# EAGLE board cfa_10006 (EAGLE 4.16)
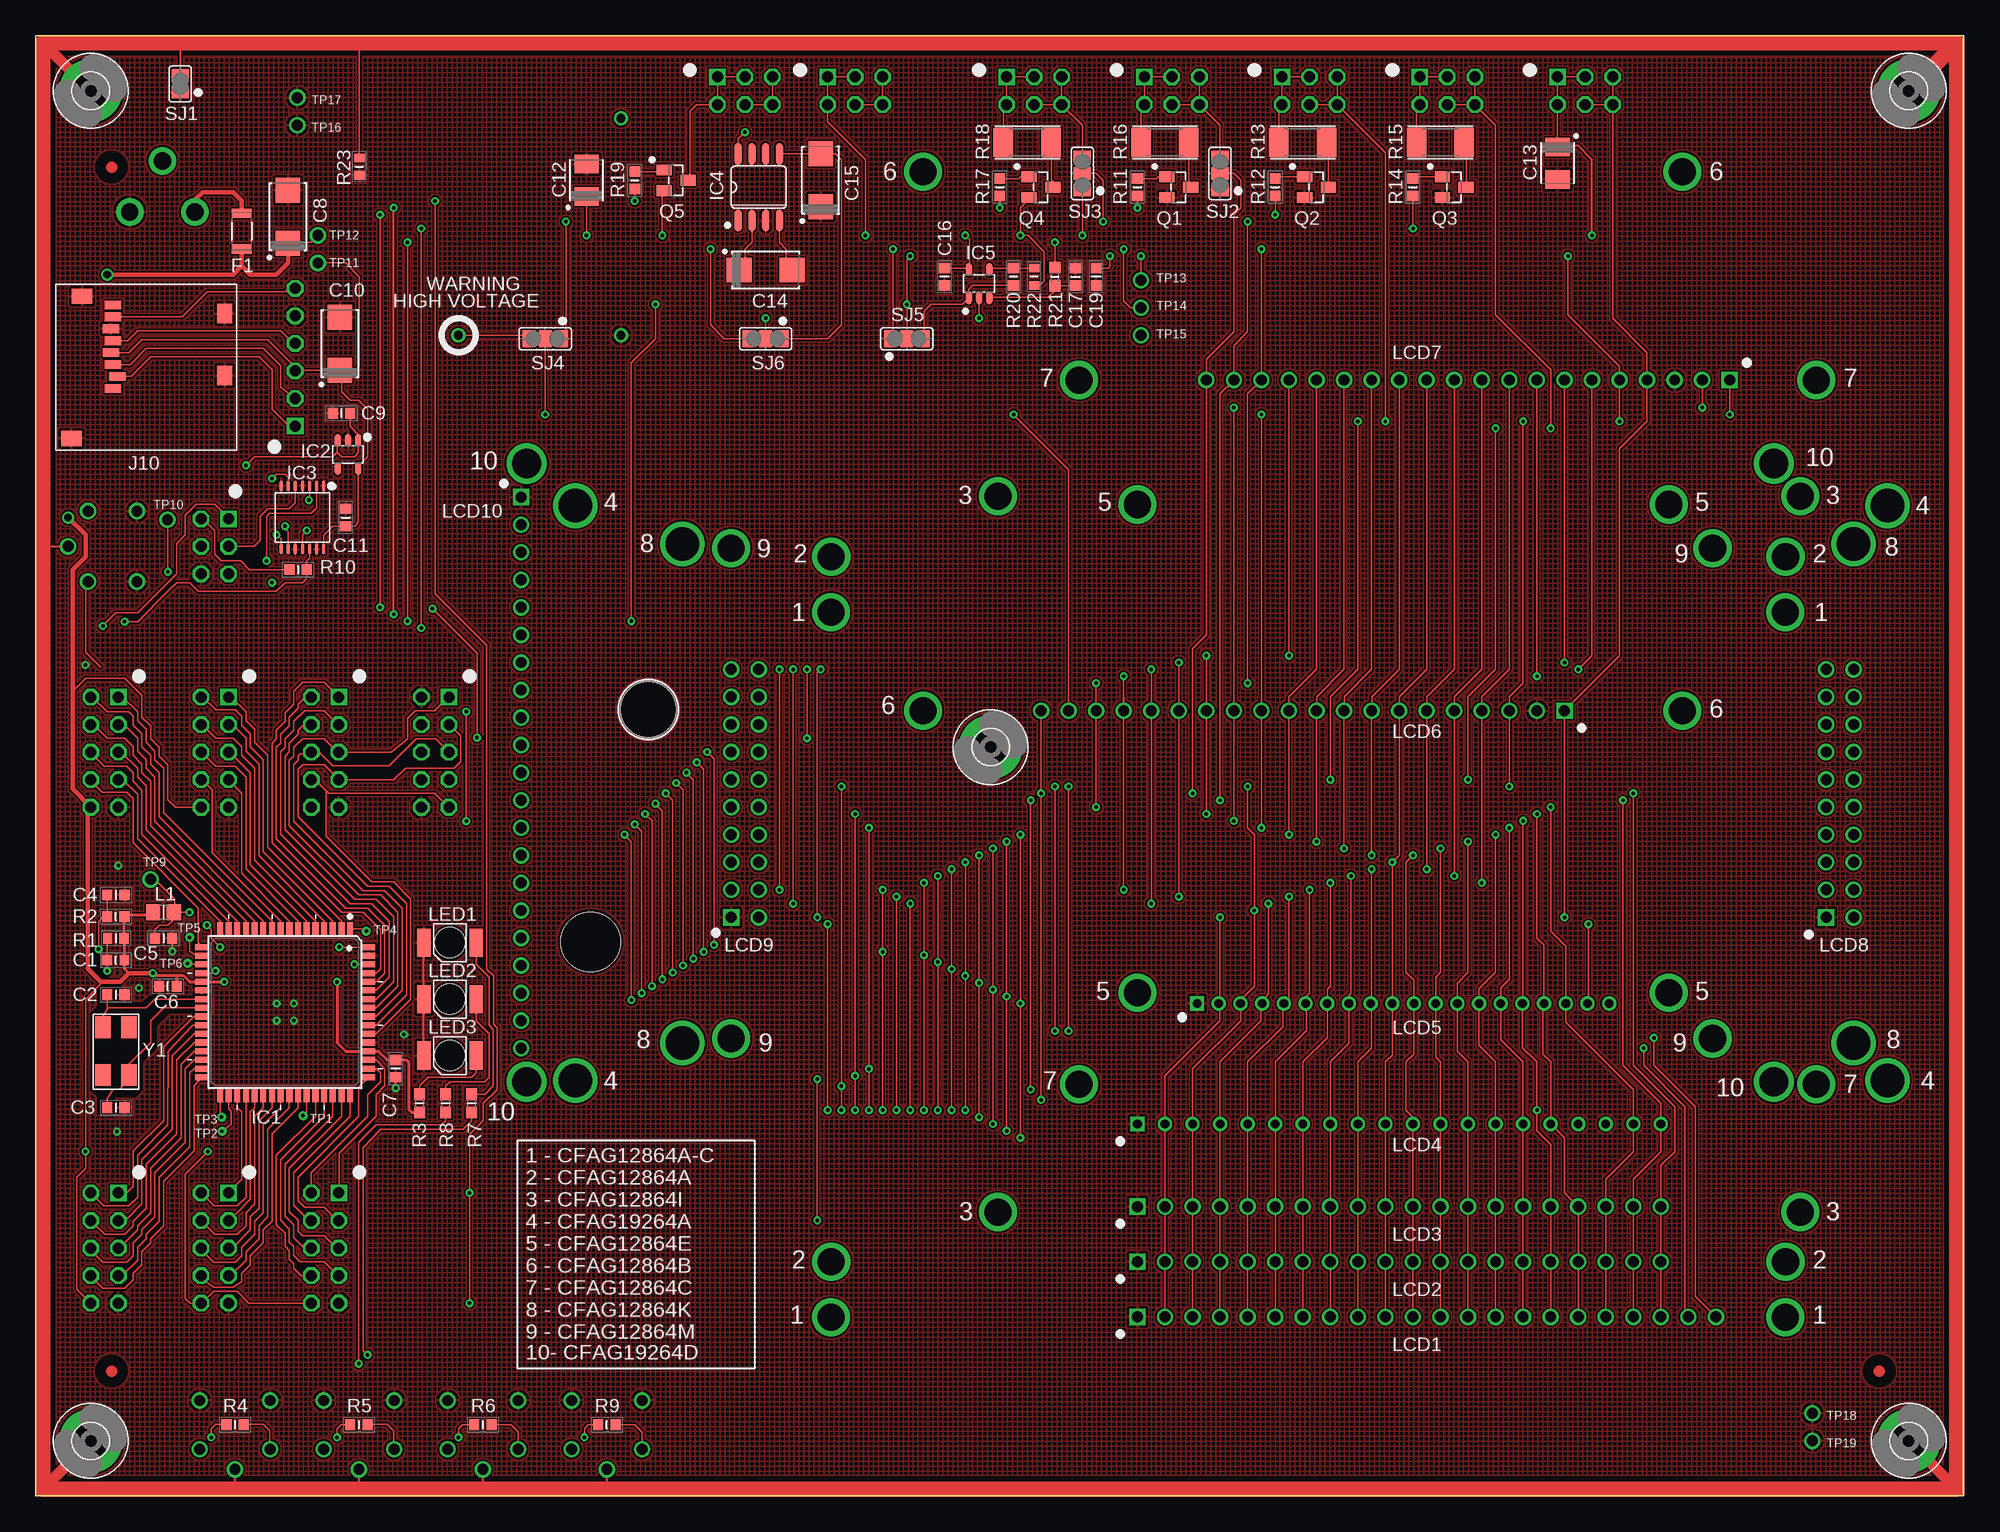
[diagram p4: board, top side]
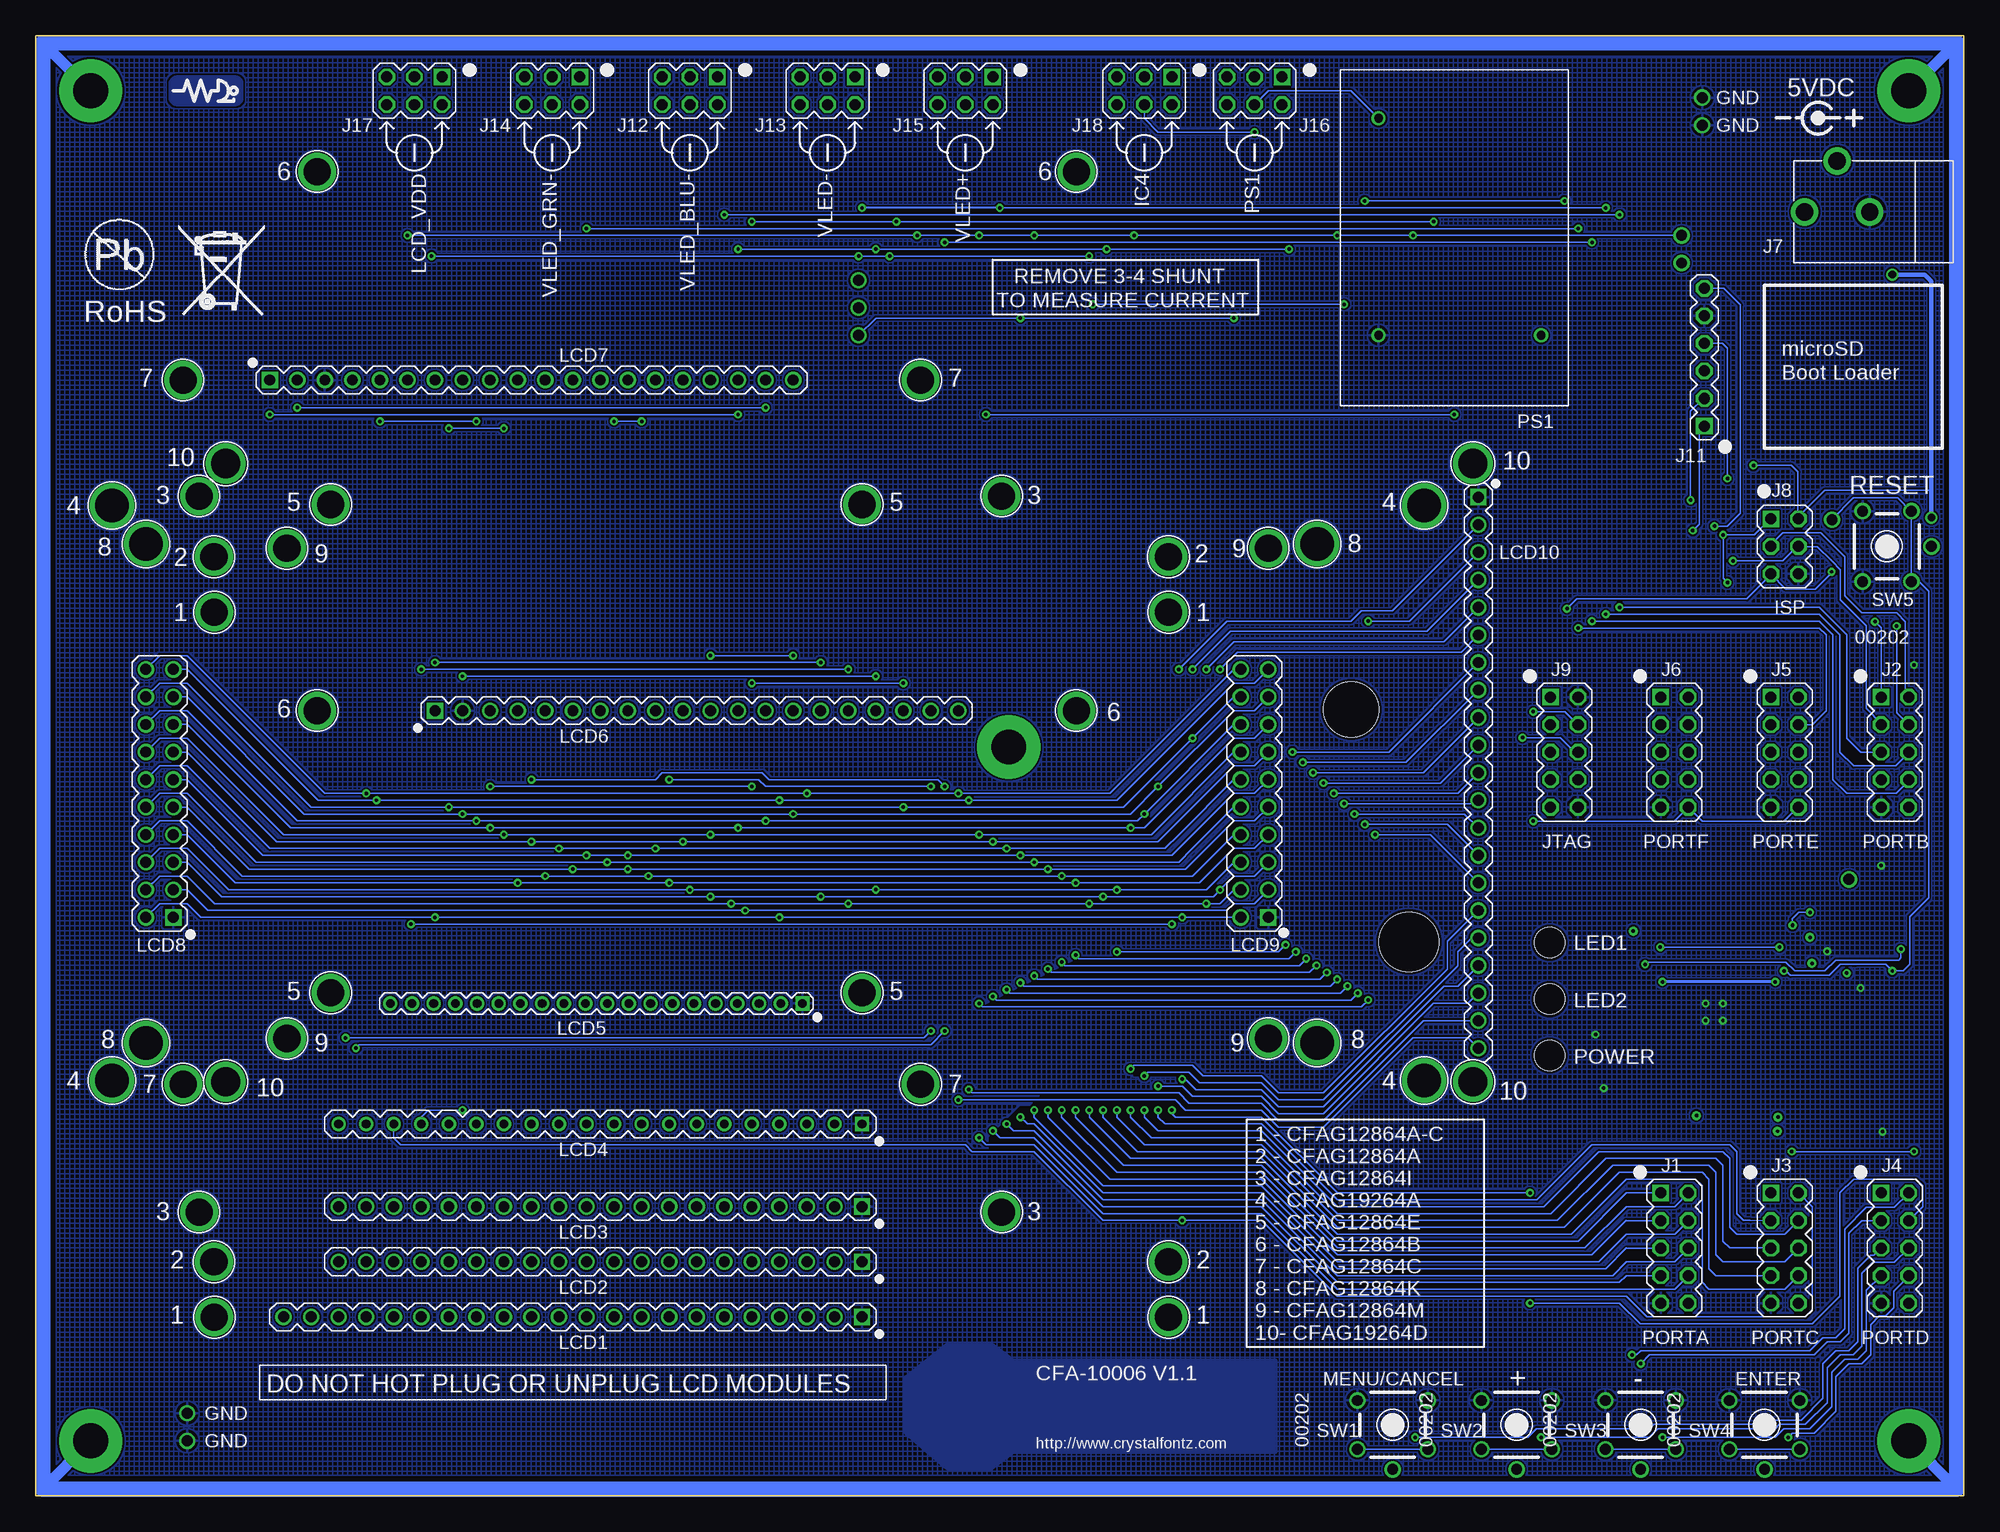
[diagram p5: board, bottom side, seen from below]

Size 177.8 x 134.62 mm. Coordinates in mm from the lower left corner, seen from the top.
Outline: 0,0 177.76,0 177.76,134.62 0,134.62
Outline: 0,0 177.8,0 177.8,134.62 0,134.62
Outline: 0,134.62 0,0
Copper layers ((1*16)): Top 0.035mm / dielectric 1.5mm / Bottom 0.035mm
Design rules "default": minimum track width 6mil, minimum drill 0.32mm, track to track 6mil, track to pad 6mil, pad to pad 6mil, via to via 6mil, smd to smd 6mil, copper to edge 10mil, drill to drill 6mil, minimum pad ring 10mil, minimum via ring 8mil, stop-mask expansion 4mil, vias tented up to drill 0mil, thermal gap 10mil
Holes 5.08 mm at 56.5,72.5
tRestrict: area 5.5,10 to 8.5,13; area 5.5,121 to 8.5,124; area 168.5,10 to 171.5,13; area 5.1,35.2 to 16.2,46.7
bRestrict: area 64.8,38.1 to 76.5,39.7; area 64.1,28.3 to 89.9,37.1; area 55.2,45.1 to 90.5,50.2

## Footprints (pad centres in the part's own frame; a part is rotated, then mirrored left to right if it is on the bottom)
EVQPB = drill 1 round: A -2.25,3.25; A' -2.25,-3.25; B 2.25,3.25; B' 2.25,-3.25; G 4.1,0
CAPC1608X90N = smd 0.9 x 0.95: 1 -0.8,0; 2 0.8,0
CAPC1608X87N = smd 0.95 x 1: 1 -0.8,0; 2 0.8,0
CAPMP6032X250N = smd 2.3 x 2.25: 1 -2.45,0; 2 2.45,0
CAPMP3528X210N = smd 1.7 x 2.25: 1 -1.5,0; 2 1.5,0
RESC3216X85N = smd 0.85 x 1.8: 1 -1.65,0; 2 1.65,0
3,2-PAD = drill 3.2 pad 5.842 round: B3,2 0,0
TQFP64-AEB = smd 1.194 x 0.559: 1 -7.7,6; 2 -7.7,5.2; 3 -7.7,4.4; 4 -7.7,3.6; 5 -7.7,2.8; 6 -7.7,2; 7 -7.7,1.2; 8 -7.7,0.4; 9 -7.7,-0.4; 10 -7.7,-1.2; 11 -7.7,-2; 12 -7.7,-2.8; 13 -7.7,-3.6; 14 -7.7,-4.4; 15 -7.7,-5.2; 16 -7.7,-6; 33 7.7,-6; 34 7.7,-5.2; 35 7.7,-4.4; 36 7.7,-3.6; 37 7.7,-2.8; 38 7.7,-2; 39 7.7,-1.2; 40 7.7,-0.4; 41 7.7,0.4; 42 7.7,1.2; 43 7.7,2; 44 7.7,2.8; 45 7.7,3.6; 46 7.7,4.4; 47 7.7,5.2; 48 7.7,6 | smd 0.559 x 1.194: 17 -6,-7.7; 18 -5.2,-7.7; 19 -4.4,-7.7; 20 -3.6,-7.7; 21 -2.8,-7.7; 22 -2,-7.7; 23 -1.2,-7.7; 24 -0.4,-7.7; 25 0.4,-7.7; 26 1.2,-7.7; 27 2,-7.7; 28 2.8,-7.7; 29 3.6,-7.7; 30 4.4,-7.7; 31 5.2,-7.7; 32 6,-7.7; 49 6,7.7; 50 5.2,7.7; 51 4.4,7.7; 52 3.6,7.7; 53 2.8,7.7; 54 2,7.7; 55 1.2,7.7; 56 0.4,7.7; 57 -0.4,7.7; 58 -1.2,7.7; 59 -2,7.7; 60 -2.8,7.7; 61 -3.6,7.7; 62 -4.4,7.7; 63 -5.2,7.7; 64 -6,7.7
SOT23-5L = smd 0.55 x 1.2: 1 -0.95,-1.3; 2 0,-1.3; 3 0.95,-1.3; 4 0.95,1.3; 5 -0.95,1.3
TSSOP14 = smd 0.305 x 0.991: 1 -1.95,-2.918; 2 -1.3,-2.918; 3 -0.65,-2.918; 4 0,-2.918; 5 0.65,-2.918; 6 1.3,-2.918; 7 1.95,-2.918; 8 1.95,2.918; 9 1.3,2.918; 10 0.65,2.918; 11 0,2.918; 12 -0.65,2.918; 13 -1.3,2.918; 14 -1.95,2.918
SO08 = smd 0.66 x 2.032: 1 -1.905,-3.073; 2 -0.635,-3.073; 3 0.635,-3.073; 4 1.905,-3.073; 5 1.905,3.073; 6 0.635,3.073; 7 -0.635,3.073; 8 -1.905,3.073
MA05-2 = drill 1.016 square: 1 -5.08,-1.27 | drill 1.016 octagon: 2 -5.08,1.27; 3 -2.54,-1.27; 4 -2.54,1.27; 5 0,-1.27; 6 0,1.27; 7 2.54,-1.27; 8 2.54,1.27; 9 5.08,-1.27; 10 5.08,1.27
PJ-102AH = drill 1.6 pad 2.54 round: 1 -3,0; 2 3,0; 3 0,4.7
MA03-2 = drill 1.016 square: 1 -2.54,-1.27 | drill 1.016 octagon: 2 -2.54,1.27; 3 0,-1.27; 4 0,1.27; 5 2.54,-1.27; 6 2.54,1.27
3M_MICROSD = smd 0.8 x 1.5: 1 -6.89,10.3; 2 -5.79,9.9; 3 -4.69,10.3; 4 -3.59,10.5; 5 -2.49,10.3; 6 -1.39,10.5; 7 -0.29,10.3; 8 0.81,10.3 | smd 1.8 x 1.4: GND1 0,0; GND2 -5.7,0 | smd 1.4 x 1.9: GND3 -11.5,14.15; GND4 1.6,13.15
MA06-1 = drill 1.016 square: 1 -6.35,0 | drill 1.016 octagon: 2 -3.81,0; 3 -1.27,0; 4 1.27,0; 5 3.81,0; 6 6.35,0
R0805 = smd 1.3 x 1.5: 1 -0.95,0; 2 0.95,0
CFAG12864A-C-PLATED-HOLES = drill 1 square: 1 0,0 | drill 1 round: 2 -2.54,0; 3 -5.08,0; 4 -7.62,0; 5 -10.16,0; 6 -12.7,0; 7 -15.24,0; 8 -17.78,0; 9 -20.32,0; 10 -22.86,0; 11 -25.4,0; 12 -27.94,0; 13 -30.48,0; 14 -33.02,0; 15 -35.56,0; 16 -38.1,0; 17 -40.64,0; 18 -43.18,0; 19 -45.72,0; 20 -48.26,0; 21 -50.8,0; 22 -53.34,0 | drill 2.5 round: P$1 -59.73,64.96; P$2 28.27,64.96; P$3 -59.73,-0.04; P$4 28.27,-0.04
CFAG12864A-PLATED-HOLES = drill 1 square: 1 0,0 | drill 1 round: 2 -2.54,0; 3 -5.08,0; 4 -7.62,0; 5 -10.16,0; 6 -12.7,0; 7 -15.24,0; 8 -17.78,0; 9 -20.32,0; 10 -22.86,0; 11 -25.4,0; 12 -27.94,0; 13 -30.48,0; 14 -33.02,0; 15 -35.56,0; 16 -38.1,0; 17 -40.64,0; 18 -43.18,0; 19 -45.72,0; 20 -48.26,0 | drill 2.5 round: H1 -59.76,65; H2 28.24,65; H3 28.24,0; H4 -59.76,0
CFAG12864I-PLATED-HOLES = drill 1 square: 1 0,0 | drill 1 round: 2 -2.54,0; 3 -5.08,0; 4 -7.62,0; 5 -10.16,0; 6 -12.7,0; 7 -15.24,0; 8 -17.78,0; 9 -20.32,0; 10 -22.86,0; 11 -25.4,0; 12 -27.94,0; 13 -30.48,0; 14 -33.02,0; 15 -35.56,0; 16 -38.1,0; 17 -40.64,0; 18 -43.18,0; 19 -45.72,0; 20 -48.26,0 | drill 2.5 round: P$1 -61.13,65.5; P$2 12.87,65.5; P$3 -61.13,-0.5; P$4 12.87,-0.5
CFAG19264A-PLATED-HOLES = drill 0.8 square: 1 48.26,0 | drill 0.8 round: 2 45.72,0; 3 43.18,0; 4 40.64,0; 5 38.1,0; 6 35.56,0; 7 33.02,0; 8 30.48,0; 9 27.94,0; 10 25.4,0; 11 22.86,0; 12 20.32,0; 13 17.78,0; 14 15.24,0; 15 12.7,0; 16 10.16,0; 17 7.62,0; 18 5.08,0; 19 2.54,0; 20 0,0 | drill 3.1 round: P$1 -20.9,57; P$2 100.1,57; P$3 -20.9,4; P$4 100.1,4
CFAG12864E-PLATED-HOLES = drill 0.8 square: 1 38,0 | drill 0.8 round: 2 36,0; 3 34,0; 4 32,0; 5 30,0; 6 28,0; 7 26,0; 8 24,0; 9 22,0; 10 20,0; 11 18,0; 12 16,0; 13 14,0; 14 12,0; 15 10,0; 16 8,0; 17 6,0; 18 4,0; 19 2,0; 20 0,0 | drill 2.5 round: P$1 -5.5,46; P$2 43.5,46; P$3 -5.5,1; P$4 43.5,1
CFAG12864B-PLATED-HOLES = drill 1 square: 1 0,0 | drill 1 round: 2 2.54,0; 3 5.08,0; 4 7.62,0; 5 10.16,0; 6 12.7,0; 7 15.24,0; 8 17.78,0; 9 20.32,0; 10 22.86,0; 11 25.4,0; 12 27.94,0; 13 30.48,0; 14 33.02,0; 15 35.56,0; 16 38.1,0; 17 40.64,0; 18 43.18,0; 19 45.72,0; 20 48.26,0 | drill 2.5 round: P$1 -10.87,49.7; P$2 59.13,49.7; P$3 -10.87,0; P$4 59.13,0
CFAG12864C-PLATED-HOLES = drill 1 square: 1 0,0 | drill 1 round: 2 2.54,0; 3 5.08,0; 4 7.62,0; 5 10.16,0; 6 12.7,0; 7 15.24,0; 8 17.78,0; 9 20.32,0; 10 22.86,0; 11 25.4,0; 12 27.94,0; 13 30.48,0; 14 33.02,0; 15 35.56,0; 16 38.1,0; 17 40.64,0; 18 43.18,0; 19 45.72,0; 20 48.26,0 | drill 2.5 round: P$1 -8,0; P$2 60,0; P$3 -8,-64.92; P$4 60,-64.92
CFAG12864K-PLATED-HOLES = drill 1 square: 1 0,0 | drill 1 round: 2 -2.54,0; 3 0,2.54; 4 -2.54,2.54; 5 0,5.08; 6 -2.54,5.08; 7 0,7.62; 8 -2.54,7.62; 9 0,10.16; 10 -2.54,10.16; 11 0,12.7; 12 -2.54,12.7; 13 0,15.24; 14 -2.54,15.24; 15 0,17.78; 16 -2.54,17.78; 17 0,20.32; 18 -2.54,20.32; 19 0,22.86; 20 -2.54,22.86 | drill 3.1 round: P$1 -2.54,34.43; P$2 105.46,34.43; P$3 -2.54,-11.57; P$4 105.46,-11.57
CFAG12864M-PLATED-HOLES = drill 1 square: 1 0,0 | drill 1 round: 2 -2.54,0; 3 0,2.54; 4 -2.54,2.54; 5 0,5.08; 6 -2.54,5.08; 7 0,7.62; 8 -2.54,7.62; 9 0,10.16; 10 -2.54,10.16; 11 0,12.7; 12 -2.54,12.7; 13 0,15.24; 14 -2.54,15.24; 15 0,17.78; 16 -2.54,17.78; 17 0,20.32; 18 -2.54,20.32; 19 0,22.86; 20 -2.54,22.86 | drill 2.5 round: P$1 -90.5,34.03; P$2 0,34.03; P$3 -90.5,-11.17; P$4 0,-11.17
CFAG19264D-PLATED-HOLES = drill 1 square: 1 0,0 | drill 1 round: 2 0,-2.54; 3 0,-5.08; 4 0,-7.62; 5 0,-10.16; 6 0,-12.7; 7 0,-15.24; 8 0,-17.78; 9 0,-20.32; 10 0,-22.86; 11 0,-25.4; 12 0,-27.94; 13 0,-30.48; 14 0,-33.02; 15 0,-35.56; 16 0,-38.1; 17 0,-40.64; 18 0,-43.18; 19 0,-45.72; 20 0,-48.26; 21 0,-50.8 | drill 2.7 round: P$1 -0.5,3.1; P$2 -0.5,-53.9; P$3 -115.5,3.1; P$4 -115.5,-53.9 | hole 5.5: -6.4,-41
T776_LED_BOTTOM = smd 1.2 x 2.6: A -2.4,0; K 2.4,0 | hole 2.8: 0,0
CFAIEL2 = drill 0.8 round: 1 0,0; 2 20,0; 3 20,15
SOT23 = smd 1 x 1.4: 1 -0.95,-1.1; 2 0.95,-1.1; 3 0,1.1
RESC1608X50N = smd 0.85 x 1: 1 -0.75,0; 2 0.75,0
RESC1608X38N = smd 0.95 x 1: 1 -0.8,0; 2 0.8,0
R0603 = smd 1.1 x 1: 1 -0.85,0; 2 0.85,0
R2010 = smd 1.8 x 2.7: 1 -2.2,0; 2 2.2,0
RESC1608X55N = smd 0.8 x 0.95: 1 -0.8,0; 2 0.8,0
SJ = smd 1.168 x 1.6: 1 -0.762,0; 2 0.762,0
SJ_2 = smd 1.168 x 1.6: 1 -1.524,0; 2 0,0; 3 1.524,0
VIA-3.2MM-HOLE = drill 0.32 round: 1 0,0
VIA-1MM-HOLE = drill 1 round: 1 0,0
ECX-64 = smd 2 x 1.4: 1 -2.2,-1.2; 2 2.2,-1.2; 3 2.2,1.2; 4 -2.2,1.2

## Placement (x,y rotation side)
+  00202  [EVQPB]  41.24,6.55 270 bottom
-  00202  [EVQPB]  29.81,6.55 270 bottom
C1  00204  [CAPC1608X90N]  7.4,49.4 180 top
C2  00127  [CAPC1608X87N]  7.4,46.2 0 top
C3  00127  [CAPC1608X87N]  7.4,35.8 0 top
C4  00133  [CAPC1608X87N]  7.4,55.4 0 top
C5  00133  [CAPC1608X87N]  11.8,51.4 0 top
C6  00133  [CAPC1608X87N]  12.2,47 180 top
C7  00133  [CAPC1608X87N]  33.2,39.4 270 top
C8  00154  [CAPMP6032X250N]  23.27,117.92 90 top
C9  00133  [CAPC1608X87N]  28.2,99.8 180 top
C10  00154  [CAPMP6032X250N]  28.07,106.22 90 top
C11  00133  [CAPC1608X87N]  28.6,90.2 90 top
C12  00140  [CAPMP3528X210N]  50.8,121.28 90 top
C13  00140  [CAPMP3528X210N]  140.34,122.87 270 top
C14  00154  [CAPMP6032X250N]  67.31,113.03 0 top
C15  00154  [CAPMP6032X250N]  72.39,121.28 90 top
C16  00133  [CAPC1608X87N]  83.82,112.39 270 top
C17  00147  [CAPC1608X87N]  95.89,112.39 90 top
C19  00133  [CAPC1608X87N]  97.79,112.39 270 top
ENTER  00202  [EVQPB]  18.38,6.55 270 bottom
F1  00199  [RESC3216X85N]  19,116.6 270 top
H1  MOUNT-PAD-ROUND3.2  [3,2-PAD]  172.72,5.08 0 top
H2  MOUNT-PAD-ROUND3.2  [3,2-PAD]  172.72,129.54 0 top
H3  MOUNT-PAD-ROUND3.2  [3,2-PAD]  5.08,129.54 0 top
H4  MOUNT-PAD-ROUND3.2  [3,2-PAD]  5.08,5.08 0 top
H5  MOUNT-PAD-ROUND3.2  [3,2-PAD]  88.06,69.03 0 top
IC1  00121  [TQFP64-AEB]  23,44.6 270 top
IC2  00156  [SOT23-5L]  28.8,96 180 top
IC3  00157  [TSSOP14]  24.6,90.2 180 top
IC4  00153  [SO08]  66.67,120.65 0 top
IC5  00250  [SOT23-5L]  87,111.76 0 top
J1  00144-10-NI  [MA05-2]  26.68,22.85 270 bottom
J2  00144-10-NI  [MA05-2]  6.36,68.57 270 bottom
J3  00144-10-NI  [MA05-2]  16.52,22.85 270 bottom
J4  00144-10-NI  [MA05-2]  6.36,22.85 270 bottom
J5  00144-10-NI  [MA05-2]  16.52,68.57 270 bottom
J6  00144-10-NI  [MA05-2]  26.68,68.57 270 bottom
J7  00142  [PJ-102AH]  11.68,118.38 0 bottom
J8  00144-6-NI  [MA03-2]  16.52,87.54 270 bottom
J9  00144-10-NI  [MA05-2]  36.84,68.57 270 bottom
J10  00155  [3M_MICROSD]  17.44,108.99 90 top
J11  00145-6-NI  [MA06-1]  23.93,104.98 90 bottom
J12  00144-6  [MA03-2]  117.47,129.54 180 bottom
J13  00144-6  [MA03-2]  104.78,129.54 180 bottom
J14  00144-6  [MA03-2]  130.18,129.54 180 bottom
J15  00144-6  [MA03-2]  92.08,129.54 180 bottom
J16  00144-6  [MA03-2]  65.41,129.54 180 bottom
J17  00144-6  [MA03-2]  142.88,129.54 180 bottom
J18  00144-6  [MA03-2]  75.56,129.54 180 bottom
L1  00148  [R0805]  11.8,53.8 0 top
LCD1  00152  [CFAG12864A-C-PLATED-HOLES]  101.6,16.51 0 bottom
LCD2  00100  [CFAG12864A-PLATED-HOLES]  101.6,21.59 0 bottom
LCD3  00231  [CFAG12864I-PLATED-HOLES]  101.6,26.67 0 bottom
LCD4  00111  [CFAG19264A-PLATED-HOLES]  149.86,34.29 0 bottom
LCD5  00108  [CFAG12864E-PLATED-HOLES]  145.1,45.4 0 bottom
LCD6  00102  [CFAG12864B-PLATED-HOLES]  140.97,72.39 0 bottom
LCD7  00232  [CFAG12864C-PLATED-HOLES]  156.21,102.87 0 bottom
LCD8  00233  [CFAG12864K-PLATED-HOLES]  165.1,53.34 0 bottom
LCD9  00109  [CFAG12864M-PLATED-HOLES]  64.14,53.34 0 bottom
LCD10  00247  [CFAG19264D-PLATED-HOLES]  44.77,92.08 0 bottom
LED1  00180  [T776_LED_BOTTOM]  38.2,51 180 top
LED2  00180  [T776_LED_BOTTOM]  38.2,45.8 180 top
LED3  00229  [T776_LED_BOTTOM]  38.2,40.6 180 top
MENU/CANCEL  00202  [EVQPB]  52.67,6.55 270 bottom
PS1  00114  [CFAIEL2]  53.98,127 270 bottom
Q1  00130  [SOT23]  105.41,120.65 270 top
Q2  00130  [SOT23]  118.11,120.65 270 top
Q3  00130  [SOT23]  130.81,120.65 270 top
Q4  00129  [SOT23]  92.71,120.65 270 top
Q5  00129  [SOT23]  59.05,121.28 270 top
R1  00203  [RESC1608X50N]  7.4,51.4 0 top
R2  00134  [RESC1608X38N]  7.4,53.4 180 top
R3  00137  [R0603]  35.4,36.2 270 top
R4  00134  [RESC1608X38N]  18.38,6.55 180 top
R5  00134  [RESC1608X38N]  29.81,6.55 180 top
R6  00134  [RESC1608X38N]  41.24,6.55 180 top
R7  00249  [R0603]  40.2,36.2 270 top
R8  00249  [R0603]  37.8,36.2 270 top
R9  00134  [RESC1608X38N]  52.67,6.55 180 top
R10  00135  [RESC1608X38N]  24.2,85.4 0 top
R11  00134  [RESC1608X38N]  101.6,120.65 90 top
R12  00134  [RESC1608X38N]  114.3,120.65 90 top
R13  00151  [R2010]  116.84,124.78 180 top
R14  00134  [RESC1608X38N]  127,120.65 90 top
R15  00151  [R2010]  129.54,124.78 180 top
R16  00151  [R2010]  104.14,124.78 180 top
R17  00134  [RESC1608X38N]  88.9,120.65 90 top
R18  00151  [R2010]  91.44,124.78 180 top
R19  00134  [RESC1608X38N]  55.24,121.28 90 top
R20  00135  [RESC1608X38N]  90.17,112.39 270 top
R21  00195  [R0603]  93.98,112.39 270 top
R22  00135  [RESC1608X55N]  92.08,112.39 270 top
R23  00191  [RESC1608X55N]  29.84,122.56 90 top
SJ1  [SJ]  13.34,130.18 90 top
SJ2  [SJ_2]  109.22,121.92 90 top
SJ3  [SJ_2]  96.52,121.92 90 top
SJ4  [SJ_2]  46.99,106.68 180 top
SJ5  [SJ_2]  80.33,106.68 0 top
SJ6  [SJ_2]  67.31,106.68 180 top
SW5  00202  [EVQPB]  7.09,87.54 0 bottom
TP1  TP-VIA-3.2MM  [VIA-3.2MM-HOLE]  24.66,35.06 0 top
TP2  TP-VIA-3.2MM  [VIA-3.2MM-HOLE]  17.18,33.62 0 top
TP3  TP-VIA-3.2MM  [VIA-3.2MM-HOLE]  17.14,34.92 0 top
TP4  TP-VIA-3.2MM  [VIA-3.2MM-HOLE]  30.48,52.07 0 top
TP5  TP-VIA-3.2MM  [VIA-3.2MM-HOLE]  14.2,51.5 0 top
TP6  TP-VIA-3.2MM  [VIA-3.2MM-HOLE]  14,49.1 0 top
TP9  TP-VIA-1.0MM  [VIA-1MM-HOLE]  10.6,56.84 0 top
TP10  TP-VIA-1.0MM  [VIA-1MM-HOLE]  12.16,89.99 0 top
TP11  TP-VIA-1.0MM  [VIA-1MM-HOLE]  26.04,113.67 0 top
TP12  TP-VIA-1.0MM  [VIA-1MM-HOLE]  26.04,116.2 0 top
TP13  TP-VIA-1.0MM  [VIA-1MM-HOLE]  101.92,112.08 0 top
TP14  TP-VIA-1.0MM  [VIA-1MM-HOLE]  101.92,109.54 0 top
TP15  TP-VIA-1.0MM  [VIA-1MM-HOLE]  101.92,107 0 top
TP16  TP-VIA-1.0MM  [VIA-1MM-HOLE]  24.13,126.36 0 top
TP17  TP-VIA-1.0MM  [VIA-1MM-HOLE]  24.13,128.91 0 top
TP18  TP-VIA-1.0MM  [VIA-1MM-HOLE]  163.83,7.62 0 top
TP19  TP-VIA-1.0MM  [VIA-1MM-HOLE]  163.83,5.08 0 top
Y1  00126  [ECX-64]  7.4,41 90 top

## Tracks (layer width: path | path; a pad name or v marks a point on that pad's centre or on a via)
+3V3
  Top 0.152: J10.4 8.6,105.4 9.8,106.6 21.4,106.6 23.8,104.2 23.8,103.8 | IC3.14 26.55,88.55 27.4,89.4 C11.1 29.4,89.4 29.75,89.75 IC2.5 | 29.75,94.95 30.6,95.8 30.6,100.2 29.8,101 29,101 28.2,101.8 28.2,103.4 | 24.03,103.77 C10.1 28.07,103.53 | 23.89,103.71 J11.3 | TP11.1 28.57,113.67 29.84,112.39 29.84,104.14 29.21,103.5 28.26,103.5
  Top 0.203: 29.75,94.95 IC2.5 | 24.03,103.77 23.83,103.77 23.8,103.8 23.89,103.71
  Top 0.254: 28.07,103.53 28.2,103.4
  Top 0.305: 27.99,103.77 27.94,103.82 | C10.1 27.99,103.77 | 27.99,103.77 28.26,103.5
+5V  (via drill 0.32, 0.7)
  Top 0.152: 13,47.4 C6.1 | 8.2,51.4 R1.2 | J3.10 14.23,17.77 13.8,18.2 13.8,29.68 v15.88,31.75 | J1.10 19.63,17.77 18.6,18.85 16.4,18.85 15.27,17.77 | J4.10 3.8,19.06 3.8,29.4 4.6,30.2 v4.6,31.75 4.6,45.8 6.2,47.4 | J5.10 12.91,63.49 12.2,64.2 12.2,67.4 11.4,68.2 11.4,69 10.6,69.8 10.6,71 9.8,71.8 9.8,73.8 8.2,75.4 4.6,75.4 3.4,74.2 | C9.1 29,98.6 29.75,97.85 IC2.1 29.75,96.15 29.4,95.8 28.2,95.8 27.8,96.2 | 27.8,96.2 27.8,97.4 | 27.8,96.2 27.4,95.8 20.2,95.8 v19.4,95 | TP12.1 25.4,115.57 23.5,115.57 | J17.3 J17.1 J17.2 140.34,124.46 | v96.52,116.2 SJ3.1 | 91.44,119.44 90.81,118.75 v90.81,116.2 91.5,116.2 93,114.7 93,112 92.59,111.59 R22.2 | v76.52,116.2 76.52,123.19 73.03,126.68 J18.2 J18.1 J18.3 | Q5.2 57.95,120.48 57.78,120.65 v57.78,116.2 | v50.8,116.2 C12.1 | C16.1 86,113.19 86,113.2 86.05,113.16 IC5.5 86.08,113.1 86.1,113.1 86.1,115.83 v85.72,116.2 | 8.15,53.35 R2.1 8.4,53.6 | L1.1 10.8,53.8 10.6,53.6 | 30.6,41 IC1.52 | v39.7,62.2 v39.7,72.3 | R10.1 19.7,85.4 18.9,86.2 17.1,86.2 16.5,86.8 16.5,89 15.3,90.2 15.25,90.15 J8.2
  Top 0.203: J3.10 15.27,17.77 | 27.8,97.4 27.85,97.35 IC2.3 | v143.51,116.2 143.51,123.19 142.24,124.46 140.34,124.46 | 6.2,47.4
  Top 0.254: 8.2,51.4 C1.1 8.2,48.6 8.6,48.2 | R3.2 34.65,35.35 34.4,35.6 34.4,40 34.2,40.2 C7.1 32.4,40.2 31.6,41 30.6,41 28.6,41 27.8,41.8 v27.8,47.4 | 140.34,124.46 C13.1 | Q4.2 91.7,119.7 91.44,119.44 | 13,48 11,48 v10.8,48.2 | 13,48 13.6,48 14.2,47.4 IC1.21 v17.4,47.4 | 13,48 13,47.4 | R1.2 8.15,53.35 | 8.4,53.6 10.6,53.6
  Top 0.305: 23.26,115.34 23.2,115.4 C8.1 | C8.1 | 23.5,115.57 23.39,115.47 C8.1
  Top 0.406: v10.8,48.2 8.6,48.2 7.8,47.4 6.2,47.4 6,47.4 4.8,48.6 4.8,63.2 J2.10 3.4,65.18 3.4,74.2 3.4,85.4 4.6,86.6 4.6,88.6 v3,90.2 | 19,113.4 F1.2 | 19,113.4 18.2,112.6 v6.6,112.6 | C8.1 23.27,113.67 22.2,112.6 19.8,112.6 19,113.4
  Bottom 0.152: v143.51,116.2 v96.52,116.2 v90.81,116.2 v85.72,116.2 v76.52,116.2 v57.78,116.2 v50.8,116.2 TP12.1 | 4.45,31.75 v4.6,31.75 v15.88,31.75 | J5.10 15.29,63.49 15.3,63.5 16.6,62.2 24.1,62.2 25.39,63.49 J6.10 26.7,62.2 v39.7,62.2 | J9.4 35.59,71.11 35.6,71.1 36.8,72.3 v39.7,72.3 | 3,92.7 12.8,92.7 15.25,90.25 J8.2 15.28,90.08 15.3,90.1 15.3,94.4 15.9,95 v19.4,95
  Bottom 0.254: v17.4,47.4 v27.8,47.4
  Bottom 0.406: v6.6,112.6 3.6,112.6 3,112 3,92.7 v3,90.2
ADC0
  Top 0.152: IC1.61 31.4,48.2 31.8,48.6 31.8,52.2 30.2,53.8 28.2,53.8 21.8,60.2 21.8,69.4 22.2,69.8 22.2,70.6 23,71.4 23,72.2 23.8,73 23.8,74.2 24.6,75 26.6,75 J6.1
  Bottom 0.152: J6.1
AVCC  (via drill 0.32, 0.35)
  Top 0.152: v17,50.6 16.2,51.4 16.2,52.2 v15.8,52.6 | C5.1 11,52.2 11.4,52.6 12.2,52.6 12.6,53 12.6,53.8 L1.2 12.8,53.8 | 12.8,53.8 v14.2,53.8 | TP9.1 10.96,56.84 12.8,55 12.8,53.8 | v28,50.6 IC1.64
  Bottom 0.152: v14.2,53.8 15.2,53.8 15.8,53.2 15.8,53.18 | 15.8,53.18 v15.8,52.6 | 15.8,53.18 15.88,53.18 | v17,50.6 v28,50.6
FOO  (via drill 0.32)
  Top 0.152: v12.6,50.2 C5.2 | C2.2 | 17.4,109 17.41,108.99 J10.GND1 | 8.26,46.2 8.25,46.2 C2.2 | IC1.22 | IC1.63 | IC1.53
  Top 0.203: v33.2,37.6 C7.2 | LED1.K LED2.K LED3.K 35.8,41.4 35.4,41.8 | 30.6,41.8 | IC1.53 30.6,41.8 | J10.GND3 3.29,97.91
  Top 0.254: 28.13,108.67 28.2,108.6 | C10.2 28.13,108.67 | 28.13,108.67 28.01,108.79 | 17.4,109 17.41,108.99 J10.GND1
  other vias: 23.81,45.4 7.62,58.1 7.5,33.58 22.23,45.4 4.6,76.6 9.53,46.83 22.23,43.81 23.81,43.81 33.97,42.55
  pour Bottom (rank 2, hatched): 1.91,132.72 175.9,132.72 175.9,1.91 1.91,1.91
  pour Top (rank 2, hatched): 1.91,132.72 175.9,132.72 175.9,1.91 1.91,1.91
GND
  pour Bottom: 158.75,130.18 arc-90 159.38,130.81 164.78,130.81 arc-90 165.42,130.18 165.42,128.91 arc-90 164.78,128.27 159.38,128.27 arc-90 158.75,128.91
GND1
  pour Bottom (rank 2): 97.54,5.84 97.54,10.92 93.73,13.97 89.66,13.97 87.63,12.45 63.5,12.45 63.5,4.06 87.63,4.06 89.66,2.54 93.73,2.54
GNDA
  Top 0.152: 29.84,133.99 R23.2
  Top 0.203: 18.41,0.64 ENTER.G | 29.84,0.64 -.G | 41.27,0.64 +.G | MENU/CANCEL.G 52.7,2.54 52.7,0.64 | SW5.G 0.72,87.54 0.64,87.63 | 13.34,133.99 SJ1.2
  Top 0.406: SJ1.2 12.7,130.81
  Top 1.016: H3.B3,2 1.27,133.35 0.64,133.35 | H1.B3,2 177.16,0.64 | H4.B3,2 0.64,0.64
  Top 1.422: 177.16,133.99 29.84,133.99 13.34,133.99 0.64,133.99 0.64,133.35 0.64,87.63 0.64,0.64 18.41,0.64 29.84,0.64 41.27,0.64 52.7,0.64 177.16,0.64 177.16,133.99 | H2.B3,2 177.16,133.99
  Bottom 1.016: 0.64,133.99 H3.B3,2 | 177.16,133.99 H2.B3,2 | 177.16,0.64 H1.B3,2 | 0.64,0.64 H4.B3,2
  Bottom 1.422: 0.64,133.99 177.16,133.99 177.16,0.64 0.64,0.64 0.64,133.99
LCD_CS1\  (via drill 0.32)
  Top 0.152: IC1.39 21.8,35.8 20.6,34.6 20.6,26.53 19.8,25.73 19.8,24.53 18.2,22.93 17.85,22.93 J3.5 | LCD1.15 LCD2.15 LCD3.15 LCD4.15 137.16,40.01 135.89,41.27 | 135.89,41.27 135.84,41.33 | LCD6.12 v113.03,61.59 | v156.21,99.69 LCD7.1 | LCD6.12 113.05,73.64 | v113.03,99.69 LCD6.12 | v76.83,61.59 v76.83,39.37 v76.83,35.56 | v135.89,61.59 135.89,47.62 135.1,46.83 LCD5.15 135.1,42.07 135.89,41.27
  Bottom 0.152: LCD9.15 65.41,69.85 67.31,69.85 75.56,61.59 v76.83,61.59 v113.03,61.59 v135.89,61.59 154.31,61.59 163.83,71.12 LCD8.15 | v156.21,99.69 v113.03,99.69 | J3.5 21.59,22.86 22.23,23.5 22.23,30.48 22.86,31.11 33.02,31.11 38.1,26.04 57.78,26.04 64.77,33.02 74.93,33.02 76.83,34.92 v76.83,35.56 | v76.83,39.37 76.52,39.69 71.12,39.69 70.17,38.73 64.77,38.73 63.18,37.15 59.05,37.15 47.62,48.58 47.62,51.12 LCD10.16
LCD_CS2\  (via drill 0.32)
  Top 0.152: J3.4 16.51,24.13 18.6,24.13 19.4,24.93 19.4,26.13 20.2,26.93 20.2,35 21,35.8 IC1.38 | LCD1.16 LCD2.16 LCD3.16 139.7,32.38 138.43,33.66 v138.43,35.56 138.43,40.01 137.1,41.34 LCD5.16 137.1,45.66 137.16,45.72 v137.16,62.23 | LCD6.13 v110.49,62.23 | LCD7.2 v153.67,100.33 | LCD6.13 110.5,73.64 | v110.49,100.33 LCD6.13 | v75.56,62.87 v75.56,38.73 v75.56,35.56
  Bottom 0.152: LCD9.16 67.3,71.13 v75.56,62.87 76.2,62.23 v110.49,62.23 v137.16,62.23 153.67,62.23 163.83,72.39 166.37,72.39 LCD8.16 | v153.67,100.33 v110.49,100.33 | J3.4 16.51,24.13 20.95,24.13 21.59,24.77 21.59,31.11 22.23,31.75 33.66,31.75 38.73,26.67 57.78,26.67 64.77,33.66 74.3,33.66 75.56,34.92 v75.56,35.56 | LCD4.17 142.24,34.92 141.6,35.56 v138.43,35.56 | v75.56,38.73 75.25,39.05 71.44,39.05 70.48,38.1 64.77,38.1 63.18,36.51 59.05,36.51 46.67,48.9 46.67,50.16 45.4,51.44 LCD10.17
LCD_CS3\  (via drill 0.32)
  Top 0.152: J3.2 16.45,26.73 18.6,26.73 19.4,27.53 IC1.36 | v72.07,25.4 v72.07,38.42
  Bottom 0.152: LCD4.18 144.78,33.02 144.15,32.38 92.08,32.38 91.44,31.75 85.72,31.75 79.38,25.4 v72.07,25.4 64.77,25.4 57.78,18.41 31.11,18.41 29.21,16.51 14.61,16.51 13.97,17.14 13.97,26.67 J3.2 | v72.07,38.42 71.75,38.42 70.8,37.47 64.77,37.47 63.18,35.88 59.05,35.88 47.94,46.99 46.67,46.99 LCD10.18
LCD_CS4\
  Top 0.152: J3.1 19,29.21 19,35.4 18.6,35.8 IC1.35
LCD_D0  (via drill 0.32)
  Top 0.152: IC1.51 | IC1.51 | IC1.51 31.4,40.2 32.2,39.4 32.2,37.8 31.4,37 31.4,35 28,31.6 28,27.98 J1.1 | v119.38,56.52 119.38,46.99 119.1,46.71 LCD5.7 119.1,42.26 116.84,40.01 LCD4.7 LCD3.7 LCD2.7 LCD1.7 | LCD6.4 133.37,73.64 | v133.35,56.52 LCD6.4 | LCD6.4 133.37,73.68 135.89,76.2 LCD7.9 | v81.92,35.56 v81.92,49.85 v81.92,56.52 | v61.59,50.16 61.59,66.99 v60.96,67.63
  Bottom 0.152: LCD9.7 65.41,59.69 67.31,59.69 70.48,56.52 v81.92,56.52 v119.38,56.52 v133.35,56.52 159.38,56.52 163.83,60.96 LCD8.7 | J1.1 31.11,27.93 31.11,27.94 35.56,23.5 57.78,23.5 64.77,30.48 77.47,30.48 81.92,34.92 v81.92,35.56 | v81.92,49.85 81.6,49.53 62.23,49.53 v61.59,50.16 | LCD10.8 51.44,67.63 v60.96,67.63
LCD_D1  (via drill 0.32)
  Top 0.152: IC1.50 | IC1.50 | IC1.50 31.4,39.4 31.8,39 31.8,38.2 30.6,37 30.6,35 25.4,29.8 J1.2 | v121.28,57.15 121.28,46.35 121.1,46.17 LCD5.8 121.1,41.72 119.38,40.01 LCD4.8 LCD3.8 LCD2.8 LCD1.8 | LCD6.5 130.82,73.64 | v130.81,57.15 LCD6.5 | LCD6.5 130.83,73.68 133.35,76.2 LCD7.10 | v83.19,35.56 v83.19,49.21 v83.19,57.15 | v60.64,49.53 60.64,66.04 v60.01,66.67
  Bottom 0.152: LCD9.8 67.32,60.97 69.85,58.42 71.12,57.15 v83.19,57.15 v121.28,57.15 v130.81,57.15 158.75,57.15 163.83,62.23 166.37,62.23 LCD8.8 | v83.19,35.56 83.19,34.92 78.11,29.84 64.77,29.84 57.78,22.86 34.92,22.86 31.11,26.67 26.67,26.67 J1.2 | v83.19,49.21 82.87,48.9 61.28,48.9 v60.64,49.53 | LCD10.9 49.85,66.67 v60.01,66.67
LCD_D2  (via drill 0.32)
  Top 0.152: IC1.49 | IC1.49 29.8,37.7 29.8,35 24.2,29.4 24.2,27.2 24.8,26.6 26.6,26.6 27.81,25.39 J1.3 | LCD1.9 LCD2.9 LCD3.9 LCD4.9 121.92,40.01 123.19,41.27 123.19,45.72 LCD5.9 123.19,46.35 v123.19,57.78 | v128.27,57.78 LCD6.6 128.29,73.68 130.81,76.2 LCD7.11 | v84.45,35.56 v84.45,48.58 v84.45,57.78 | v59.69,48.9 59.69,65.09 v59.05,65.72
  Bottom 0.152: LCD9.9 65.41,62.23 67.31,62.23 71.75,57.78 v84.45,57.78 v123.19,57.78 v128.27,57.78 158.12,57.78 163.83,63.5 LCD8.9 | J1.3 31.11,25.39 31.11,25.4 34.29,22.23 57.78,22.23 64.77,29.21 78.74,29.21 84.45,34.92 v84.45,35.56 | v84.45,48.58 84.14,48.26 60.33,48.26 v59.69,48.9 | LCD10.10 48.26,65.72 v59.05,65.72
LCD_D3  (via drill 0.32)
  Top 0.152: 29,35 IC1.48 | 29,35 29,35.8 | 29,35 23.8,29.8 23.8,26.8 25.21,25.39 J1.4 | 125.09,45.72 125.1,45.72 LCD5.10 125.09,45.72 | 125.09,45.72 v125.09,58.42 125.73,59.05 LCD6.7 | LCD6.7 125.75,73.64 | LCD1.10 LCD2.10 LCD3.10 LCD4.10 124.46,40.01 125.09,40.64 125.09,45.72 | LCD6.7 125.75,73.68 128.27,76.2 LCD7.12 | v85.72,35.56 v85.72,47.94 v85.72,58.42 | v58.74,48.26 58.74,64.14 v58.1,64.77
  Bottom 0.152: LCD9.10 67.32,63.51 71.12,59.69 72.39,58.42 v85.72,58.42 v125.09,58.42 157.48,58.42 163.83,64.77 166.37,64.77 LCD8.10 | J1.4 26.67,24.13 31.11,24.13 33.66,21.59 57.78,21.59 64.77,28.57 79.38,28.57 85.72,34.92 v85.72,35.56 | v85.72,47.94 85.41,47.62 59.37,47.62 v58.74,48.26 | LCD10.11 46.67,64.77 v58.1,64.77
LCD_D4  (via drill 0.32)
  Top 0.152: 28.2,35 IC1.47 | 28.2,35 23.4,30.2 23.4,26.2 24.2,25.4 24.2,24.4 24.6,24 26.6,24 27.75,22.85 27.93,22.85 J1.5 | 28.2,35 28.2,35.4 | LCD6.8 123.2,73.64 | v123.19,59.05 LCD6.8 | LCD6.8 123.21,73.68 125.73,76.2 LCD7.13 | LCD1.11 LCD2.11 LCD3.11 LCD4.11 127,34.92 126.36,35.56 126.36,40.01 127.1,40.74 LCD5.11 127.1,47.53 126.36,48.26 126.36,58.42 v127,59.05 | v87,34.92 v87,47.31 v87,59.05 | v57.78,47.62 57.78,63.18 v57.15,63.82
  Bottom 0.152: LCD9.11 65.41,64.77 67.31,64.77 73.03,59.05 v87,59.05 v123.19,59.05 v127,59.05 156.84,59.05 163.83,66.04 LCD8.11 | J1.5 31.11,22.85 31.11,22.86 33.02,20.95 57.78,20.95 64.77,27.94 79.38,27.94 85.72,34.29 86.36,34.29 v87,34.92 | v87,47.31 86.68,46.99 58.42,46.99 v57.78,47.62 | LCD10.12 45.09,63.82 v57.15,63.82
LCD_D5  (via drill 0.32)
  Top 0.152: 27.4,35 IC1.46 | 27.4,35 27.4,35.8 | 27.4,35 23,30.6 23,25.8 23.8,25 23.8,23.8 24.75,22.85 25.39,22.85 J1.6 | v129.54,59.69 129.54,48.26 129.1,47.82 LCD5.12 129.1,40.45 129.54,40.01 LCD4.12 LCD3.12 LCD2.12 LCD1.12 | LCD6.9 120.67,73.64 | v120.65,59.69 LCD6.9 | LCD6.9 120.67,73.68 123.19,76.2 LCD7.14 | v88.27,34.29 v88.27,46.67 v88.27,59.69 | v56.83,46.99 56.83,62.23 v56.2,62.87
  Bottom 0.152: LCD9.12 67.32,66.05 72.39,60.96 73.66,59.69 v88.27,59.69 v120.65,59.69 v129.54,59.69 156.21,59.69 163.83,67.31 166.37,67.31 LCD8.12 | J1.6 26.67,21.59 31.11,21.59 32.38,20.32 57.78,20.32 64.77,27.3 79.38,27.3 85.72,33.66 87.63,33.66 v88.27,34.29 | v88.27,46.67 87.95,46.35 57.47,46.35 v56.83,46.99 | LCD10.13 46.04,62.87 v56.2,62.87
LCD_D6  (via drill 0.32)
  Top 0.152: 26.6,35 IC1.45 | 26.6,35 26.6,35.8 | 26.6,35 22.6,31 22.6,25.4 23.4,24.6 23.4,23.4 23.8,23 23.8,22.2 24.4,21.6 26.6,21.6 27.89,20.31 J1.7 | LCD1.13 LCD2.13 LCD3.13 LCD4.13 132.08,40.01 131.1,40.99 LCD5.13 131.1,47.28 132.08,48.26 v132.08,60.33 | LCD6.10 118.12,73.64 | v118.11,60.33 LCD6.10 | LCD6.10 118.13,73.68 120.65,76.2 LCD7.15 | v89.53,33.66 v89.53,46.04 v89.53,60.33 | v55.88,46.35 55.88,61.28 v55.24,61.91
  Bottom 0.152: LCD9.13 65.41,67.31 67.31,67.31 74.3,60.33 v89.53,60.33 v118.11,60.33 v132.08,60.33 155.57,60.33 163.83,68.58 LCD8.13 | J1.7 31.11,20.31 31.11,20.32 31.75,19.68 57.78,19.68 64.77,26.67 79.38,26.67 85.72,33.02 88.9,33.02 v89.53,33.66 | v89.53,46.04 89.22,45.72 56.52,45.72 v55.88,46.35 | LCD10.14 47.62,61.91 v55.24,61.91
LCD_D7  (via drill 0.32)
  Top 0.152: IC1.44 25.8,35.8 25.8,35 22.2,31.4 22.2,25 23,24.2 23,23 23.4,22.6 23.4,21.8 23.8,21.4 23.8,21 24.49,20.31 J1.8 | LCD6.11 115.59,73.68 118.11,76.2 LCD7.16 | LCD1.14 LCD2.14 LCD3.14 LCD4.14 134.62,40.01 133.1,41.53 LCD5.14 133.1,46.74 134.62,48.26 v134.62,60.96 | LCD6.11 115.58,73.64 | v115.57,60.96 LCD6.11 | v90.81,33.02 v90.81,45.4 v90.81,60.96 | v54.93,45.72 54.93,60.33 v54.29,60.96
  Bottom 0.152: LCD9.14 66.69,68.59 67.3,68.59 74.93,60.96 v90.81,60.96 v115.57,60.96 v134.62,60.96 154.94,60.96 163.83,69.85 166.37,69.85 LCD8.14 | J1.8 26.67,19.05 57.78,19.05 64.77,26.04 79.38,26.04 85.72,32.38 90.17,32.38 v90.81,33.02 | v54.93,45.72 55.56,45.09 90.49,45.09 v90.81,45.4 | LCD10.15 49.21,60.96 v54.29,60.96
LCD_D/I\  (via drill 0.32)
  Top 0.152: LCD1.4 LCD2.4 LCD3.4 LCD4.4 109.22,40.01 113,43.78 113,45.4 LCD5.4 113.67,46.35 v113.67,54.61 | v142.24,76.2 143.51,77.47 LCD7.6 | J3.8 15.2,20.26 15.2,20.13 16.4,19.23 18.2,19.23 19,19.73 19,20.53 19.8,21.33 19.8,22.13 21,23.33 21,24.53 21.8,25.33 21.8,33.4 24.2,35.8 IC1.42 | v80.64,35.56 v80.64,54.61 | v102.87,54.61 LCD6.16 v102.87,76.2 | v69.85,54.61 v69.85,76.2
  Bottom 0.152: LCD9.4 67.31,55.88 68.58,54.61 v69.85,54.61 v80.64,54.61 v102.87,54.61 v113.67,54.61 161.29,54.61 163.83,57.15 166.37,57.15 LCD8.4 | v102.87,76.2 v142.24,76.2 | J3.8 16.51,19.05 23.5,19.05 24.13,19.68 24.13,28.57 24.77,29.21 31.11,29.21 36.2,24.13 57.78,24.13 64.77,31.11 76.83,31.11 80.64,34.92 v80.64,35.56 | 45.09,82.23 LCD10.5 47.94,78.74 67.31,78.74 v69.85,76.2
LCD_E  (via drill 0.32)
  Top 0.152: 15.2,22.9 15.2,22.93 | 15.2,22.9 J3.6 | 15.2,22.9 15.2,22.73 16.4,21.53 18.4,21.53 19,22.13 19,22.93 20.2,24.13 20.2,25.33 21,26.13 21,34.2 22.6,35.8 IC1.40 | LCD1.6 LCD2.6 LCD3.6 LCD4.6 114.3,40.01 117.2,42.91 117.2,45.4 LCD5.6 117.1,45.98 117.47,46.35 v117.47,55.88 | v138.43,75.56 LCD7.8 | LCD6.17 100.34,73.64 | LCD6.17 v100.33,75.56 | v78.11,35.56 v78.11,50.16 v78.11,55.88 | v100.33,55.89 LCD6.17 | v62.55,50.8 62.55,67.94 v61.91,68.58
  Bottom 0.152: LCD9.6 67.31,58.42 69.85,55.88 81.28,55.88 | v78.11,55.88 81.28,55.88 | 81.28,55.88 | 81.28,55.88 97.79,55.88 99.05,55.89 v100.33,55.89 104.15,55.89 109.86,55.88 v117.47,55.88 160.02,55.88 163.83,59.69 166.37,59.69 LCD8.6 | v100.33,75.56 v138.43,75.56 | J3.6 16.51,21.59 22.23,21.59 22.86,22.23 22.86,29.84 23.5,30.48 32.38,30.48 37.47,25.4 57.78,25.4 64.77,32.38 75.56,32.38 78.11,34.92 v78.11,35.56 | v78.11,50.16 63.18,50.16 v62.55,50.8 | LCD10.7 53.02,68.58 v61.91,68.58
LCD_EL  (via drill 0.32)
  Top 0.152: IC1.28 | IC1.28 14.6,41.8 13,40.2 13,33.4 10.2,30.6 10.2,27.73 | 10.2,27.73 10.2,27.33 | 10.2,27.73 10.2,26.53 9,25.33 9,24.93 8.2,24.13 6.35,24.13 J4.4 | v40.01,17.78 v40.01,27.94 40.01,33.34 41.27,34.61 41.27,36.2 42.55,37.47 42.55,43.18 42.23,43.5 42.23,47.94 41.59,48.58 41.59,78.42 36.83,83.19 v36.83,119.38 | 55.24,120.65 R19.1 v55.24,119.38 | LCD5.19 143.19,45.4 v143.19,52.7 | v73.03,35.56 v73.03,52.7
  Bottom 0.152: v40.01,17.78 31.75,17.78 29.84,15.88 13.97,15.88 11.43,18.41 11.43,27.94 10.16,29.21 4.45,29.21 3.81,28.57 3.81,26.67 J4.4 | v36.83,119.38 v55.24,119.38 | v73.03,52.7 v143.19,52.7 | v73.03,35.56 73.03,35.24 72.71,34.92 64.77,34.92 57.78,27.94 v40.01,27.94
LCD_HVDC
  Top 0.152: 45.72,106.05 SJ4.3 45.47,106.67 45.4,106.6 45,107 PS1.3
LCD_R/W\  (via drill 0.32)
  Top 0.152: J3.7 17.8,20.33 18,20.33 19.4,21.73 19.4,22.53 20.6,23.73 20.6,24.93 21.4,25.73 21.4,33.8 23.4,35.8 IC1.41 | LCD1.5 LCD2.5 LCD3.5 LCD4.5 111.76,40.01 115,43.24 115,45.4 LCD5.5 115.25,45.4 115.57,45.72 v115.57,55.24 | v140.97,76.83 LCD7.7 | v79.38,35.56 v79.38,55.24 | v105.41,55.24 LCD6.15 v105.41,76.83 | v68.58,55.88 v68.58,76.2
  Bottom 0.152: LCD9.5 65.41,57.15 67.31,57.15 v68.58,55.88 69.22,55.24 v79.38,55.24 v105.41,55.24 v115.57,55.24 160.66,55.24 163.83,58.42 LCD8.5 | v105.41,76.83 v140.97,76.83 | J3.7 19.68,20.31 | 19.68,20.31 19.68,20.32 | 19.68,20.31 22.86,20.32 23.5,20.95 23.5,29.21 24.13,29.84 31.75,29.84 36.83,24.77 57.78,24.77 64.77,31.75 76.2,31.75 79.38,34.92 v79.38,35.56 | LCD10.6 46.35,77.79 66.99,77.79 v68.58,76.2
LCD_RST\  (via drill 0.32)
  Top 0.152: IC1.37 20.2,35.8 19.8,35.4 19.8,27.33 18.43,25.96 18.34,25.96 J3.3 | LCD1.17 LCD2.17 LCD3.17 140.97,27.94 140.97,33.02 LCD4.16 139.7,40.01 139,40.7 139,45.4 LCD5.17 139.1,45.69 139.06,45.72 139.06,50.8 138.43,51.44 v138.43,62.87 | v107.95,62.87 LCD6.14 v107.95,77.47 | v115.57,77.47 LCD7.17 | v74.3,35.56 v74.3,37.78 v74.3,65.41
  Bottom 0.152: LCD9.17 65.41,72.39 67.31,72.39 v74.3,65.41 76.83,62.87 v107.95,62.87 v138.43,62.87 153.03,62.87 163.83,73.66 LCD8.17 | v107.95,77.47 v115.57,77.47 | J3.3 19.68,25.4 20.32,25.4 20.95,26.04 20.95,31.75 21.59,32.38 34.29,32.38 39.37,27.3 57.78,27.3 64.77,34.29 73.66,34.29 74.3,34.92 v74.3,35.56 | v74.3,37.78 72.07,37.78 71.12,36.83 64.77,36.83 63.18,35.24 59.05,35.24 48.9,45.4 45.72,45.4 LCD10.19
LCD_VB+  (via drill 0.32)
  Top 0.152: LCD6.19 95.25,94.61 v90.17,99.69 | v46.99,99.69 SJ4.2
  Bottom 0.152: v46.99,99.69 v90.17,99.69
LCD_VDD  (via drill 0.32)
  Top 0.152: LCD1.2 LCD2.2 LCD3.2 LCD4.2 104.14,38.73 109.22,43.81 109.22,45.72 | J17.6 145.41,108.58 148.59,105.41 LCD7.4 148.59,99.06 146.05,96.52 146.05,77.47 LCD6.1 v140.97,53.34 | LCD5.2 109.1,45.6 109.22,45.72 | v109.22,53.34 109.22,45.72 | J17.4 J17.6 | J17.6 J17.5 | v72.07,53.34 72.07,75.88 v72.39,76.2
  Bottom 0.152: LCD9.2 v72.07,53.34 v109.22,53.34 v140.97,53.34 162.56,53.34 163.83,54.61 166.37,54.61 LCD8.2 | v72.39,76.2 67.94,80.64 56.52,80.64 55.56,81.6 52.7,81.6 LCD10.2
LCD_VEE  (via drill 0.32)
  Top 0.152: LCD1.18 LCD2.18 LCD3.18 144.78,29.21 147.32,31.75 LCD4.19 | LCD4.19 147.32,34.92 | LCD4.19 147.32,37.47 141.1,43.69 LCD5.18 141.1,50.67 139.7,52.07 v139.7,63.5 | v97.79,63.5 LCD6.18 v97.79,74.93 | v111.76,74.93 111.76,101.6 LCD7.18 v113.03,114.94 | v62.23,114.94 62.23,107.95 63.5,106.68 SJ6.3 66.04,106.68 | v100.33,114.94 100.33,110.17 100.97,109.54 TP14.1 | SJ5.1 79.06,106.88 v79.06,114.94 | v71.12,76.2 v71.12,69.85
  Bottom 0.152: LCD9.18 67.31,73.66 v71.12,69.85 77.47,63.5 v97.79,63.5 v139.7,63.5 152.4,63.5 163.83,74.93 166.37,74.93 LCD8.18 | v97.79,74.93 v111.76,74.93 | v113.03,114.94 v100.33,114.94 v79.06,114.94 v62.23,114.94 | v71.12,76.2 67.63,79.69 49.53,79.69 LCD10.4
LCD_VLED+  (via drill 0.32)
  Top 0.152: LCD1.19 LCD2.19 LCD3.19 147.32,29.21 149.86,31.75 LCD4.20 149.86,36.2 146.37,39.69 v146.37,64.14 | v109.22,64.14 109.22,101.6 LCD7.19 110.49,106.05 111.76,107.31 v111.76,117.47 | SJ3.2 97.79,121.92 98.42,121.28 v98.42,117.47 | SJ4.1 48.51,106.93 48.9,107.31 v48.9,117.47 | v91.76,37.47 v91.76,64.14
  Bottom 0.152: LCD8.19 163.83,76.2 151.76,64.14 v146.37,64.14 v109.22,64.14 v91.76,64.14 78.11,64.14 67.31,74.93 65.41,74.93 LCD9.19 | v111.76,117.47 v98.42,117.47 v48.9,117.47 | v91.76,37.47 91.44,37.15 72.39,37.15 71.44,36.2 64.77,36.2 63.18,34.61 59.05,34.61 49.85,43.81 LCD10.20
LCD_VLED-  (via drill 0.32)
  Top 0.152: LCD1.20 LCD2.20 LCD3.20 149.86,30.48 151.13,31.75 151.13,35.88 147.32,39.69 v147.32,64.77 | LCD6.20 v92.71,64.77 v92.71,36.51 | v106.68,64.77 106.68,78.11 107.95,79.38 LCD7.20 107.95,104.78 110.49,107.31 110.49,118.11 111.12,118.75 111.12,121.28 110.49,121.92 SJ2.2
  Bottom 0.152: LCD9.20 67.31,76.2 78.74,64.77 v92.71,64.77 v106.68,64.77 v147.32,64.77 151.13,64.77 163.83,77.47 166.37,77.47 LCD8.20 | v92.71,36.51 72.71,36.51 71.75,35.56 64.77,35.56 63.18,33.97 59.05,33.97 50.8,42.23 45.72,42.23 LCD10.21
LCD_VLED_BLU-  (via drill 0.32)
  Top 0.152: J12.6 J12.5 | J12.6 J12.4 | v119.38,66.04 119.38,73.66 121.92,76.2 v121.92,99.06 | LCD1.22 153.03,18.41 153.03,35.88 149.22,39.69 v149.22,42.23 | v95.25,42.86 v95.25,65.41 | v124.46,99.06 124.46,123.83 J12.6
  Bottom 0.152: v95.25,42.86 95.89,42.23 v149.22,42.23 | v95.25,65.41 110.49,65.41 111.12,66.04 v119.38,66.04 | v121.92,99.06 v124.46,99.06
LCD_VLED_GRN-  (via drill 0.32)
  Top 0.152: J14.4 J14.6 | J14.6 J14.5 | v132.08,66.04 132.08,73.66 134.62,76.2 v134.62,98.42 | J14.6 134.62,126.36 134.62,108.9 139.7,103.82 v139.7,98.42 | LCD1.21 152.08,16.83 152.08,35.88 148.27,39.69 v148.27,41.27 | v93.98,65.41 v93.98,42.86
  Bottom 0.152: v148.27,41.27 147.96,41.59 95.25,41.59 v93.98,42.86 | v132.08,66.04 120.65,66.04 120.02,66.67 110.81,66.67 110.17,66.04 94.61,66.04 v93.98,65.41 | v139.7,98.42 v134.62,98.42
LCD_VO  (via drill 0.32)
  Top 0.152: LCD1.3 LCD2.3 LCD3.3 LCD4.3 106.68,39.37 111.12,43.81 111.12,45.72 111.1,45.69 | 111.1,45.69 LCD5.3 | 111.1,45.69 112.39,46.99 v112.37,53.98 112.37,60.93 111.76,61.59 v111.76,65.41 | v135.89,65.41 LCD6.3 135.89,73.66 137.16,74.93 v137.16,99.06 | v146.05,99.06 LCD7.5 146.05,104.14 141.29,108.9 v141.29,114.3 | v101.92,114.3 TP13.1 | v80.64,114.3 80.33,113.98 v80.33,109.86 SJ5.2 | C19.1 98.91,113.19 99.06,113.35 v99.06,114.3 | v54.93,80.64 54.93,104.46 57.15,106.68 v57.15,109.86
  Bottom 0.152: v135.89,65.41 v111.76,65.41 | LCD9.3 65.41,54.61 67.31,54.61 67.94,53.98 v112.37,53.98 | v112.37,53.98 112.39,53.98 | v146.05,99.06 v137.16,99.06 | LCD8.3 163.83,55.88 161.93,53.98 v112.37,53.98 | v141.29,114.3 v101.92,114.3 v99.06,114.3 v80.64,114.3 | LCD10.3 51.12,80.64 v54.93,80.64 | v80.33,109.86 v57.15,109.86
LED1  (via drill 0.32)
  Top 0.152: IC1.26 14.5,43.4 12.2,41 12.2,34.2 9.4,31.4 9.4,27.93 | 9.4,27.93 9.4,27.73 | 9.4,27.93 9.4,27.53 8.6,26.73 6.29,26.73 J4.2 | R7.2 40.2,34.6 39.4,33.8 31.8,33.8 30.2,32.1 30.2,13.4 v30.6,13
  Bottom 0.152: v30.6,13 30.2,13 29.8,13.4 14.2,13.4 13,14.6 11.8,14.6 11,15.4 11,24.6 9,26.6 6.42,26.6 J4.2
LED2  (via drill 0.32)
  Top 0.152: IC1.27 | IC1.27 14.6,42.6 12.6,40.6 12.6,33.8 9.8,31 9.8,26.93 8.3,25.43 | 8.3,25.43 | J4.3 8.26,25.39 8.3,25.43 | v29.8,12.2 29.8,32.6 31.4,34.2 37.4,34.2 37.8,34.6 R8.2
  Bottom 0.152: J4.3 9.41,25.39 10.6,24.2 10.6,15 11.4,14.2 12.6,14.2 13.8,13 29,13 v29.8,12.2
MISO  (via drill 0.32)
  Top 0.152: J2.4 5.36,71.11 6.6,69.87 8.2,69.87 9,69.07 9,68.27 9.8,67.47 9.8,66.67 10.6,65.87 10.6,61.8 19.4,53 IC1.13 | v6.2,80.2 7.4,81.4 9.4,81.4 13,85 13,87.8 13.8,88.6 13.8,90.4 14.8,91.4 16.5,91.4 17.8,90.1 J8.1 | IC3.8 22.65,88.25 v22.2,88.6
  Bottom 0.152: J2.4 5.11,71.11 6.2,72.2 v6.2,80.2 | v21.8,84.2 22.2,84.6 v22.2,88.6 19.3,88.6 17.8,90.1 J8.1
MOSI  (via drill 0.32)
  Top 0.152: J2.3 8.16,71.11 9.4,69.87 9.4,68.67 10.2,67.87 10.2,67.07 11,66.27 11,62.2 20.2,53 IC1.12 | IC3.2 25.9,91.1 25.4,90.6 | 25.4,90.6 | 25.4,90.6 21.6,90.6 21.3,90.3 v21.3,86.2
  Bottom 0.152: 12.2,86.2 11.4,85.4 11.4,82.6 9,80.2 9,72.6 7.6,71.2 7.63,71.17 J2.3 | 12.2,86.2 | 12.2,86.2 13.5,87.5 15.2,87.5 J8.4 15.36,87.54 16.7,86.2 v21.3,86.2
N$1
  Top 0.152: IC1.23 11,45.8 10.2,45 6.68,45 | Y1.3 6.2,44.2 6.68,45 | C2.1 6.6,44.92 6.68,45
N$2
  Top 0.152: 21.6,4.4 21.63,4.37 ENTER.B' | 21.6,4.4 21.5,4.3 | 21.6,4.4 21.6,6 21,6.6 19.2,6.6 19.18,6.58 R4.1
  Bottom 0.152: 21.59,4.3 ENTER.B' | ENTER.B 21.59,4.3 | 21.59,4.3 21.59,4.29
N$3
  Top 0.152: IC1.24 11.8,45 10.6,43.8 10.6,41.8 8.6,39.8 Y1.1 7.81,37.48 7.17,37.48 7.16,37.48 6.6,36.6 C3.1
N$4
  Top 0.152: 33,4.4 33.06,4.34 -.B' | 33,4.4 32.9,4.3 | 33,4.4 33,6 32.4,6.6 30.6,6.6 30.61,6.59 R5.1
  Bottom 0.152: 33.02,4.3 -.B' | -.B 33.02,4.3 | 33.02,4.3 33.02,4.29
N$5
  Top 0.152: IC1.19 14.2,49 TP6.1
N$6
  Top 0.152: 44.51,4.3 +.B' 44.49,5.93 43.87,6.55 42.16,6.55 42.15,6.57 42.13,6.55 R6.1
  Bottom 0.152: 44.45,4.3 +.B' | +.B 44.45,4.3 | 44.45,4.3 44.45,4.29
N$7
  Top 0.152: R7.1 41.45,37.05 42.2,37.8 42.2,43 41.8,43.4 41.8,47.8 40.6,49 LED1.A
N$8
  Top 0.152: 55.94,4.3 MENU/CANCEL.B' 55.92,5.85 55.22,6.55 53.54,6.55 53.53,6.55 R9.1
  Bottom 0.152: 55.88,4.3 MENU/CANCEL.B' | MENU/CANCEL.B 55.88,4.3 | 55.88,4.3 55.88,4.29
N$9  (via drill 0.32)
  Top 0.152: v29.39,49 IC1.62 | v5.8,50.4 5.8,53 6.2,53.4 R2.2 C4.1
  Bottom 0.152: v5.8,50.4 5.8,49.6 6,49.4 9.6,49.4 9.8,49.4 11.8,49.4 12.8,48.4 15.6,48.4 16.4,49.2 29.19,49.2 v29.39,49
N$10
  Top 0.152: R8.1 37.8,37.8 38.2,38.2 41.4,38.2 41.8,38.6 41.8,42.6 40.6,43.8 LED2.A
N$11
  Top 0.152: TP1.1 25,35.4 IC1.43
N$13
  Top 0.152: IC1.34 17.8,35.74 18.02,35.42 18.02,34.26 TP2.1
N$14
  Top 0.406: J7.1 14.68,119.48 15.4,120.2 18.2,120.2 19,119.4 F1.1
  Top 0.61: F1.1 19,118.2
N$15
  Top 0.152: IC1.33 17,35.07 TP3.1
N$16
  Top 0.152: IC1.1 30.25,52.3 TP4.1
N$17
  Top 0.152: R3.1 35.4,37.8 36.2,38.6 40.2,38.6 40.6,39 LED3.A
N$18
  Top 0.152: IC1.18 14.8,49.8 14.2,50.2 TP5.1
N$21
  Top 0.152: J12.3 J12.1 J12.2 114.64,127.97 R13.2
N$23
  Top 0.152: R13.1 119.04,124.17 119.21,124 Q2.3
N$24
  Top 0.152: R12.2 114.3,121.28 114.61,121.6 Q2.1
N$25
  Top 0.152: J13.3 J13.1 J13.2 101.94,127.97 R16.2
N$26
  Top 0.152: J13.6 J13.5 | J13.6 J13.4 | SJ2.3 109.22,126.36 J13.6
N$27
  Top 0.152: J14.3 J14.1 J14.2 127.34,127.97 R15.2
N$28  (via drill 0.32)
  Top 0.152: IC4.8 64.77,125.09 v65.41,125.73 | J18.5 J18.6 J18.4
  Bottom 0.152: v65.41,125.73 74.3,125.73 75.56,127 J18.4
N$29
  Top 0.152: R15.1 131.74,124.17 131.91,124 Q3.3
N$30
  Top 0.152: R16.1 106.36,124.78 106.36,120.8 Q1.3
N$31
  Top 0.152: R11.2 103.35,121.45 103.5,121.6 104.14,121.6 Q1.1
N$32
  Top 0.152: R14.2 127,121.28 127.31,121.6 Q3.1
N$33
  Top 0.152: J15.3 J15.1 J15.2 89.24,127.97 R18.2
N$34
  Top 0.152: J15.6 J15.5 | J15.6 J15.4 | J15.6 96.52,126.36 SJ3.3
N$35
  Top 0.152: Q4.3 93.81,121.14 93.66,121.28 93.66,124.46 R18.1
N$36
  Top 0.152: R17.2 90.65,121.45 90.81,121.6 91.44,121.6 Q4.1
N$37
  Top 0.152: J16.3 J16.1 J16.2 60.96,128.27 60.33,127.64 60.33,121.42 60.16,121.25 | 60.16,121.25 60,121.1 | Q5.3 60.16,121.25
N$38
  Top 0.152: J16.4 J16.6 J16.5
  Bottom 0.152: J16.4 64.14,129.54 56.52,129.54 PS1.1
N$39
  Top 0.152: IC4.2 66.04,115.57 65.41,114.94 65.41,113.67 64.77,113.03 C14.1
N$40
  Top 0.152: Q5.1 57.95,122.39 57.78,122.56 57.31,122.08 R19.2
N$41
  Top 0.152: IC4.4 68.58,115.57 69.22,114.94 69.22,113.67 69.85,113.03 C14.2
N$42
  Top 0.152: R20.1 90.11,113.19 90.1,113.2 | R20.1 R22.1 | IC5.4 88,113 88.19,113.19 R20.1
N$43
  Top 0.152: IC4.5 72.29,123.72 72.39,123.83 C15.2 73.75,123.73 74.3,123.19 74.3,107.95 73.03,106.68 SJ6.1 68.58,106.68
N$44
  Top 0.152: R20.2 86.39,111.59 86,111.2 86,110.5 IC5.1 | IC5.1 86.1,110.4 | IC5.1 | IC5.1 86.1,110.5 | IC5.1 85.45,109.86 82.55,109.86 81.92,109.22 81.92,106.88 SJ5.3
N$45
  Top 0.152: C17.1 95.81,111.59 95.8,111.6 95.75,111.55 R21.2 93.98,111.12 93.34,110.49 88.01,110.49 88,110.5 IC5.3
PB6
  Top 0.152: J2.7 8.04,66.03 9.4,64.67 9.4,60.6 17,53 IC1.16
PD0
  Top 0.152: IC1.25 | IC1.25 14.6,44.2 11.8,41.4 11.8,34.6 9,31.8 9,28.53 8.4,27.93 J4.1
PE0
  Top 0.152: J5.1 18.02,73.65 19.4,72.27 19.4,71.47 20.2,70.67 20.2,69.47 21.4,68.27 21.4,59.8 28.2,53 IC1.2
PE1
  Top 0.152: J5.2 15.42,73.65 16.6,72.47 18.4,72.47 19,71.87 19,71.07 19.8,70.27 19.8,69.07 21,67.87 21,59.4 27.4,53 IC1.3
PE2
  Top 0.152: J5.3 18.16,71.11 19.4,69.87 19.4,68.67 20.6,67.47 20.6,59 26.6,53 IC1.4
PE4
  Top 0.152: J5.5 17.9,68.57 19.8,66.67 19.8,58.2 25,53 IC1.6
PE5
  Top 0.152: J5.6 15.3,68.57 16.6,67.27 18.4,67.27 19.4,66.27 19.4,57.8 24.2,53 IC1.7
PE6
  Top 0.152: IC1.8 23.4,53 19,57.4 19,64.8 17.79,66.01 J5.7
PE7
  Top 0.152: IC1.9 22.6,53 16.3,59.3 16.3,65.1 15.4,66 15.28,66 J5.8
PF1
  Top 0.152: IC1.60 31.4,47.4 32.2,48.2 32.2,52.6 30.6,54.2 28.6,54.2 22.2,60.6 22.2,69 22.6,69.4 22.6,70.2 23.4,71 23.4,71.8 24.2,72.6 24.2,73 24.8,73.6 25.4,73.6 25.41,73.61 J6.2
PF2
  Top 0.152: IC1.59 31.4,46.6 32.6,47.8 32.6,53 31,54.6 29,54.6 22.6,61 22.6,68.6 23,69 23,69.8 23.8,70.6 23.8,71.4 24.8,72.4 26.6,72.4 27.89,71.11 J6.3
PF3
  Top 0.152: IC1.58 31.4,45.8 33,47.4 33,53.4 31.4,55 29.4,55 23,61.4 23,68.2 23.4,68.6 23.4,69.4 24.2,70.2 24.2,70.6 24.6,71 25.4,71 25.41,71.01 J6.4
PWM0  (via drill 0.32)
  Top 0.152: IC1.17 | IC1.17 15.4,50.6 15,51 15,54.2 9,60.2 9,64.27 8.4,64.87 6.4,64.87 6.13,64.87 5.09,65.91 J2.8 | v34.29,80.64 v34.29,115.57 | 93.98,113.03 R21.1 v93.98,115.57
  Bottom 0.152: v34.29,80.64 13.34,80.64 12.06,79.38 12.06,66.04 10.79,64.77 6.23,64.77 5.09,65.91 J2.8 | v34.29,115.57 v93.98,115.57
PWM1  (via drill 0.32)
  Top 0.152: 17.8,52.2 IC1.15 17.8,53 9.8,61 9.8,65.07 9,65.87 9,66.67 8.4,67.27 6.33,67.27 5.09,68.51 J2.6 | v88.9,118.75 R17.1 | 101.6,120.02 R11.1 v101.6,118.75
  Top 0.203: v33.02,81.28 v33.02,118.75
  Bottom 0.152: v33.02,81.28 13.34,81.28 11.43,79.38 11.43,68.58 10.16,67.31 6.29,67.31 5.09,68.51 J2.6 | v33.02,118.75 v88.9,118.75
  Bottom 0.203: v88.9,118.75 v101.6,118.75
PWM2  (via drill 0.32)
  Top 0.152: J2.5 7.9,68.57 9.4,67.07 9.4,66.27 10.2,65.47 10.2,61.4 18.6,53 IC1.14 | v114.3,118.11 R12.1 | v31.75,81.92 v31.75,118.11
  Bottom 0.152: J2.5 9.52,68.57 10.79,69.85 10.79,79.38 13.34,81.92 v31.75,81.92 | v31.75,118.11 v114.3,118.11
PWM3  (via drill 0.32)
  Top 0.152: J5.4 15.36,71.11 16.6,69.87 18.2,69.87 19,69.07 19,68.27 20.2,67.07 20.2,58.6 25.8,53 IC1.5 | v127,116.84 R14.1 | v35.56,80.01 v35.56,116.84
  Bottom 0.152: J5.4 13.98,71.11 12.7,72.39 12.7,79.38 13.34,80.01 v35.56,80.01 | v35.56,116.84 v127,116.84
RESET\  (via drill 0.32)
  Top 0.152: R1.1 6.6,51.4 C1.2 v6.6,48.4 | IC1.20 16.4,48.2 v16.6,48.4 | 6,76.4 4.6,77.8 4.6,84.2 4.69,84.29 SW5.B' | v40.7,69.9 40.7,77.7 v36.6,81.8 | TP10.1 12.16,85.24 v12.2,85.2
  Bottom 0.152: v16.6,48.4 16.4,48.4 16,48 12.4,48 11.4,49 10.2,49 10,49 7.2,49 v6.6,48.4 5.6,48.4 5,49 5,53.4 3.23,55.16 3.23,83.4 4.12,84.29 SW5.B' 4.84,90.76 4.81,90.79 | 4.81,90.79 4.8,90.8 | 4.81,90.79 SW5.B 4.89,90.79 6.1,92 10.2,92 12.2,90 12.19,89.99 TP10.1 | J9.6 35.87,68.57 37.2,69.9 v40.7,69.9 | v36.6,81.8 35.7,82.7 20,82.7 17.7,85 | 17.7,85 | 17.7,85 J8.5 | v12.2,85.2 12.2,85.1 13.7,83.6 16.4,83.6 J8.5 | J8.5
SCK
  Top 0.152: J2.2 5.22,73.65 6.6,72.27 8.6,72.27 9,71.87 9,71.07 9.8,70.27 9.8,69.07 10.6,68.27 10.6,67.47 11.4,66.67 11.4,62.6 21,53 IC1.11 | IC3.5 23.95,91.55 23.4,91 21.4,91 | J8.3 20.14,87.54 20.7,88.1 20.7,90.3 21.4,91 | 21.4,91
  Bottom 0.152: 11.94,87.54 11,86.6 11,83 9.4,81.4 6.2,81.4 5.4,80.6 5.4,74.2 5.09,73.71 J2.2 | 11.94,87.54 | 11.94,87.54 13.2,88.8 16.7,88.8 17.9,87.6 17.84,87.54 J8.3
SD_MISO  (via drill 0.32)
  Top 0.152: J10.7 13.5,108.7 15.8,111 23,111 23.33,111.33 J11.6 | IC3.9 23.3,88.9 v23,89.4
  Bottom 0.152: v23,89.4 21.8,89.4 20.6,90.6 20.6,109.8 22.13,111.33 J11.6
SD_MOSI  (via drill 0.32)
  Top 0.152: J10.3 8.7,104.3 10.2,105.8 21,105.8 22.6,104.2 22.6,102.2 23.97,101.17 | 23.97,101.17 24,101.2 | IC3.3 25.25,91.85 v25.2,91.8 | 23.97,101.17 J11.2
  Bottom 0.152: J11.2 23.97,101.17 24,101.2 25.2,100 v25.2,91.8
SD_SCK  (via drill 0.32)
  Top 0.152: J10.5 8.5,106.5 9.4,107.4 22.6,107.4 23.75,106.25 J11.4 | v21.8,93.8 22.2,94.2 23,94.2 23.3,93.9 IC3.6
  Bottom 0.152: v21.8,93.8 21.8,105.8 22.25,106.25 J11.4
SD_SS\  (via drill 0.32)
  Top 0.152: J10.2 8.8,103.2 10.6,105 20.6,105 21.8,103.8 21.8,100.2 23.4,98.6 23.8,98.6 23.83,98.63 J11.1 | IC3.11 24.6,88.6 v25,89
  Bottom 0.152: v25,89 24.4,89.6 24.4,98 | J11.1 23.83,98.63 23.8,98.6 24.4,98 | 24.4,98
SS\  (via drill 0.32)
  Top 0.152: J2.1 8.02,73.65 9.4,72.27 9.4,71.47 10.2,70.67 10.2,69.47 11,68.67 11,67.87 11.8,67.07 11.8,63 21.8,53 IC1.10 | v8.2,80.6 9.4,80.6 12.2,83.4 | 12.2,83.4 | 12.2,83.4 13,84.2 14.2,84.2 15,83.4 22.2,83.4 23,84.2 24.6,84.2 25,84.6 R10.2 25,86.2 25.25,86.45 IC3.12
  Bottom 0.152: J2.1 7.63,80.03 v8.2,80.6
SW1  (via drill 0.32)
  Top 0.152: IC1.29 | IC1.29 14.6,41 13.4,39.8 13.4,33 10.6,30.2 10.6,26.13 9.4,24.93 9.4,24.53 7.8,22.93 7.6,22.93 7.6,22.88 J4.5 | R9.2 50.95,6.55 50.6,6.2 v50.6,5.4
  Bottom 0.152: v50.6,5.4 40.2,5.4 39.4,6.2 29,6.2 28.6,6.6 17.8,6.6 17.4,7 15,7 13,9 13,12.2 11.8,13.4 10.6,13.4 9.8,14.2 9.8,21 8.6,22.2 8.28,22.2 J4.5 | J4.5 7.62,22.86 | J4.5
SW2  (via drill 0.32)
  Top 0.152: IC1.30 | IC1.30 14.6,40.2 13.8,39.4 13.8,32.6 11,29.8 11,25.73 9.8,24.53 9.8,24.13 9,23.33 9,22.13 8.4,21.53 6.2,21.53 5,22.73 5,22.76 J4.6 | R6.2 39.35,6.55 39,6.2 v39,5.4
  Bottom 0.152: v39,5.4 29,5.4 28.2,6.2 17.4,6.2 17,6.6 14.6,6.6 12.6,8.6 12.6,11.8 11.4,13 10.2,13 9.4,13.8 9.4,20.52 8.38,21.54 6.4,21.54 J4.6 | J4.6 5.08,22.86 | J4.6
SW3  (via drill 0.32)
  Top 0.152: IC1.31 | IC1.31 14.6,39.4 14.2,39 14.2,32.2 11.4,29.4 11.4,25.33 10.2,24.13 10.2,23.73 9.4,22.93 9.4,21.73 8,20.33 7.61,20.33 | 7.61,20.33 7.6,20.33 | J4.7 7.61,20.33 | R5.2 28.15,6.55 27.8,6.2 v27.8,5.4
  Bottom 0.152: v27.8,5.4 17.4,5.4 16.6,6.2 14.2,6.2 12.2,8.2 12.2,11.4 11,12.6 9.8,12.6 9,13.4 9,18.94 J4.7
SW4  (via drill 0.32)
  Top 0.152: IC1.32 | IC1.32 14.6,37.8 14.6,31.8 | J4.8 5.07,20.33 5,20.33 6.2,19.13 8.2,19.13 9,19.93 9,20.53 9.8,21.33 9.8,22.53 10.6,23.33 10.6,23.73 11.8,24.93 11.8,29 14.6,31.8 | 14.6,31.8 | R4.2 17.53,6.6 16.6,6.6 16.2,6.2 v16.2,5.4
  Bottom 0.152: v16.2,5.4 15.8,5.8 13.8,5.8 11.8,7.8 11.8,11 10.6,12.2 9.4,12.2 8.6,13 8.6,15.8 7.8,16.6 7.21,16.6 6.45,17.36 6.46,18.87 5.01,20.31 | 5.01,20.31 4.99,20.33 | 5.01,20.31 J4.8
TCK
  Top 0.152: IC1.57 31.4,45 33.4,47 33.4,53.8 31.8,55.4 29.8,55.4 23.4,61.8 23.4,67.8 23.8,68.2 23.8,69 24.6,69.8 26.6,69.8 27.83,68.57 J6.5 32.77,68.57 34.3,69.8 34.3,71.7 35,72.4 36.8,72.4 38.1,73.7 38.11,73.69 J9.1
TDI
  Top 0.152: IC1.54 31.4,42.6 34.6,45.8 34.6,55 33,56.6 31,56.6 26.8,60.8 26.8,65 | J6.8 25.77,66.03 26.8,65 | 26.8,65 27,64.8 36.8,64.8 J9.9
TDO
  Top 0.152: IC1.55 31.4,43.4 34.2,46.2 34.2,54.6 32.6,56.2 30.6,56.2 24.2,62.6 24.2,67 24.6,67.4 26.6,67.4 27.95,66.05 J6.7 33.03,66.03 34.1,67.1 38.6,67.1 39.2,67.7 39.2,70.1 38.19,71.11 J9.3
TMS
  Top 0.152: IC1.56 31.4,44.2 33.8,46.6 33.8,54.2 32.2,55.8 30.2,55.8 23.8,62.2 23.8,67.4 24.2,67.8 24.2,68.2 24.4,68.4 25.2,68.4 25.4,68.6 25.41,68.59 J6.6 26.13,68.57 27.4,67.3 32.6,67.3 35.1,69.8 36.9,69.8 38.11,68.59 J9.5
VEE  (via drill 0.32)
  Top 0.152: v87,108.58 IC5.2 | SJ6.2 v67.31,108.58
  Bottom 0.152: v67.31,108.58 v87,108.58 100.33,108.58 TP15.1
(copper drawn outside any net)
  shapes: Top circle x3

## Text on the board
tPlace: 6 | 6 | WARNING | HIGH VOLTAGE | 7 | 7 | 10 | 10 | 4 | 3 | 5 | 5 | 3 | 4 | 8 | 9 | 8 | 2 | 9 | 2 | 1 | 1 | 6 | 6 | 5 | 5 | 8 | 9 | 9 | 8 | 4 | 7 | 10 | 7 | 4 | 10 | 1 - CFAG12864A-C | 2 - CFAG12864A | 3 - CFAG12864I | 4 - CFAG19264A | 3 | 3 | 5 - CFAG12864E | 6 - CFAG12864B | 2 | 2 | 7 - CFAG12864C | 8 - CFAG12864K | 1 | 1 | 9 - CFAG12864M | 10- CFAG19264D
bPlace: 5VDC | GND | GND | I | I | I | I | I | I | I | PS1 | IC4 | VLED+ | VLED- | VLED_BLU- | VLED_GRN- | LCD_VDD | 6 | 6 | REMOVE 3-4 SHUNT | TO MEASURE CURRENT | RoHS | microSD | Boot Loader | 7 | 7 | 10 | 10 | RESET | 4 | 3 | 5 | 5 | 3 | 4 | 8 | 9 | 8 | 2 | 9 | 2 | ISP | 1 | 1 | 6 | 6 | PORTB | PORTE | PORTF | JTAG | LED1 | 5 | 5 | LED2 | 8 | 9 | 9 | 8 | POWER | 10 | 4 | 7 | 10 | 7 | 4 | 1 - CFAG12864A-C | 2 - CFAG12864A | 3 - CFAG12864I | 4 - CFAG19264A | 5 - CFAG12864E | 3 | 3 | 6 - CFAG12864B | 2 | 2 | 7 - CFAG12864C | 8 - CFAG12864K | 9 - CFAG12864M | 1 | 1 | PORTD | PORTC | PORTA | 10- CFAG19264D | CFA-10006 V1.1 | DO NOT HOT PLUG OR UNPLUG LCD MODULES | GND | SW4 | SW3 | SW2 | SW1 | http://www.crystalfontz.com | GND
tNames: LCD7 | LCD10 | LCD6 | LCD9 | LCD8 | LCD5 | LCD4 | LCD3 | LCD2 | LCD1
